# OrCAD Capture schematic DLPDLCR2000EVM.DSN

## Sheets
1 P05: SDRAM memory: size D
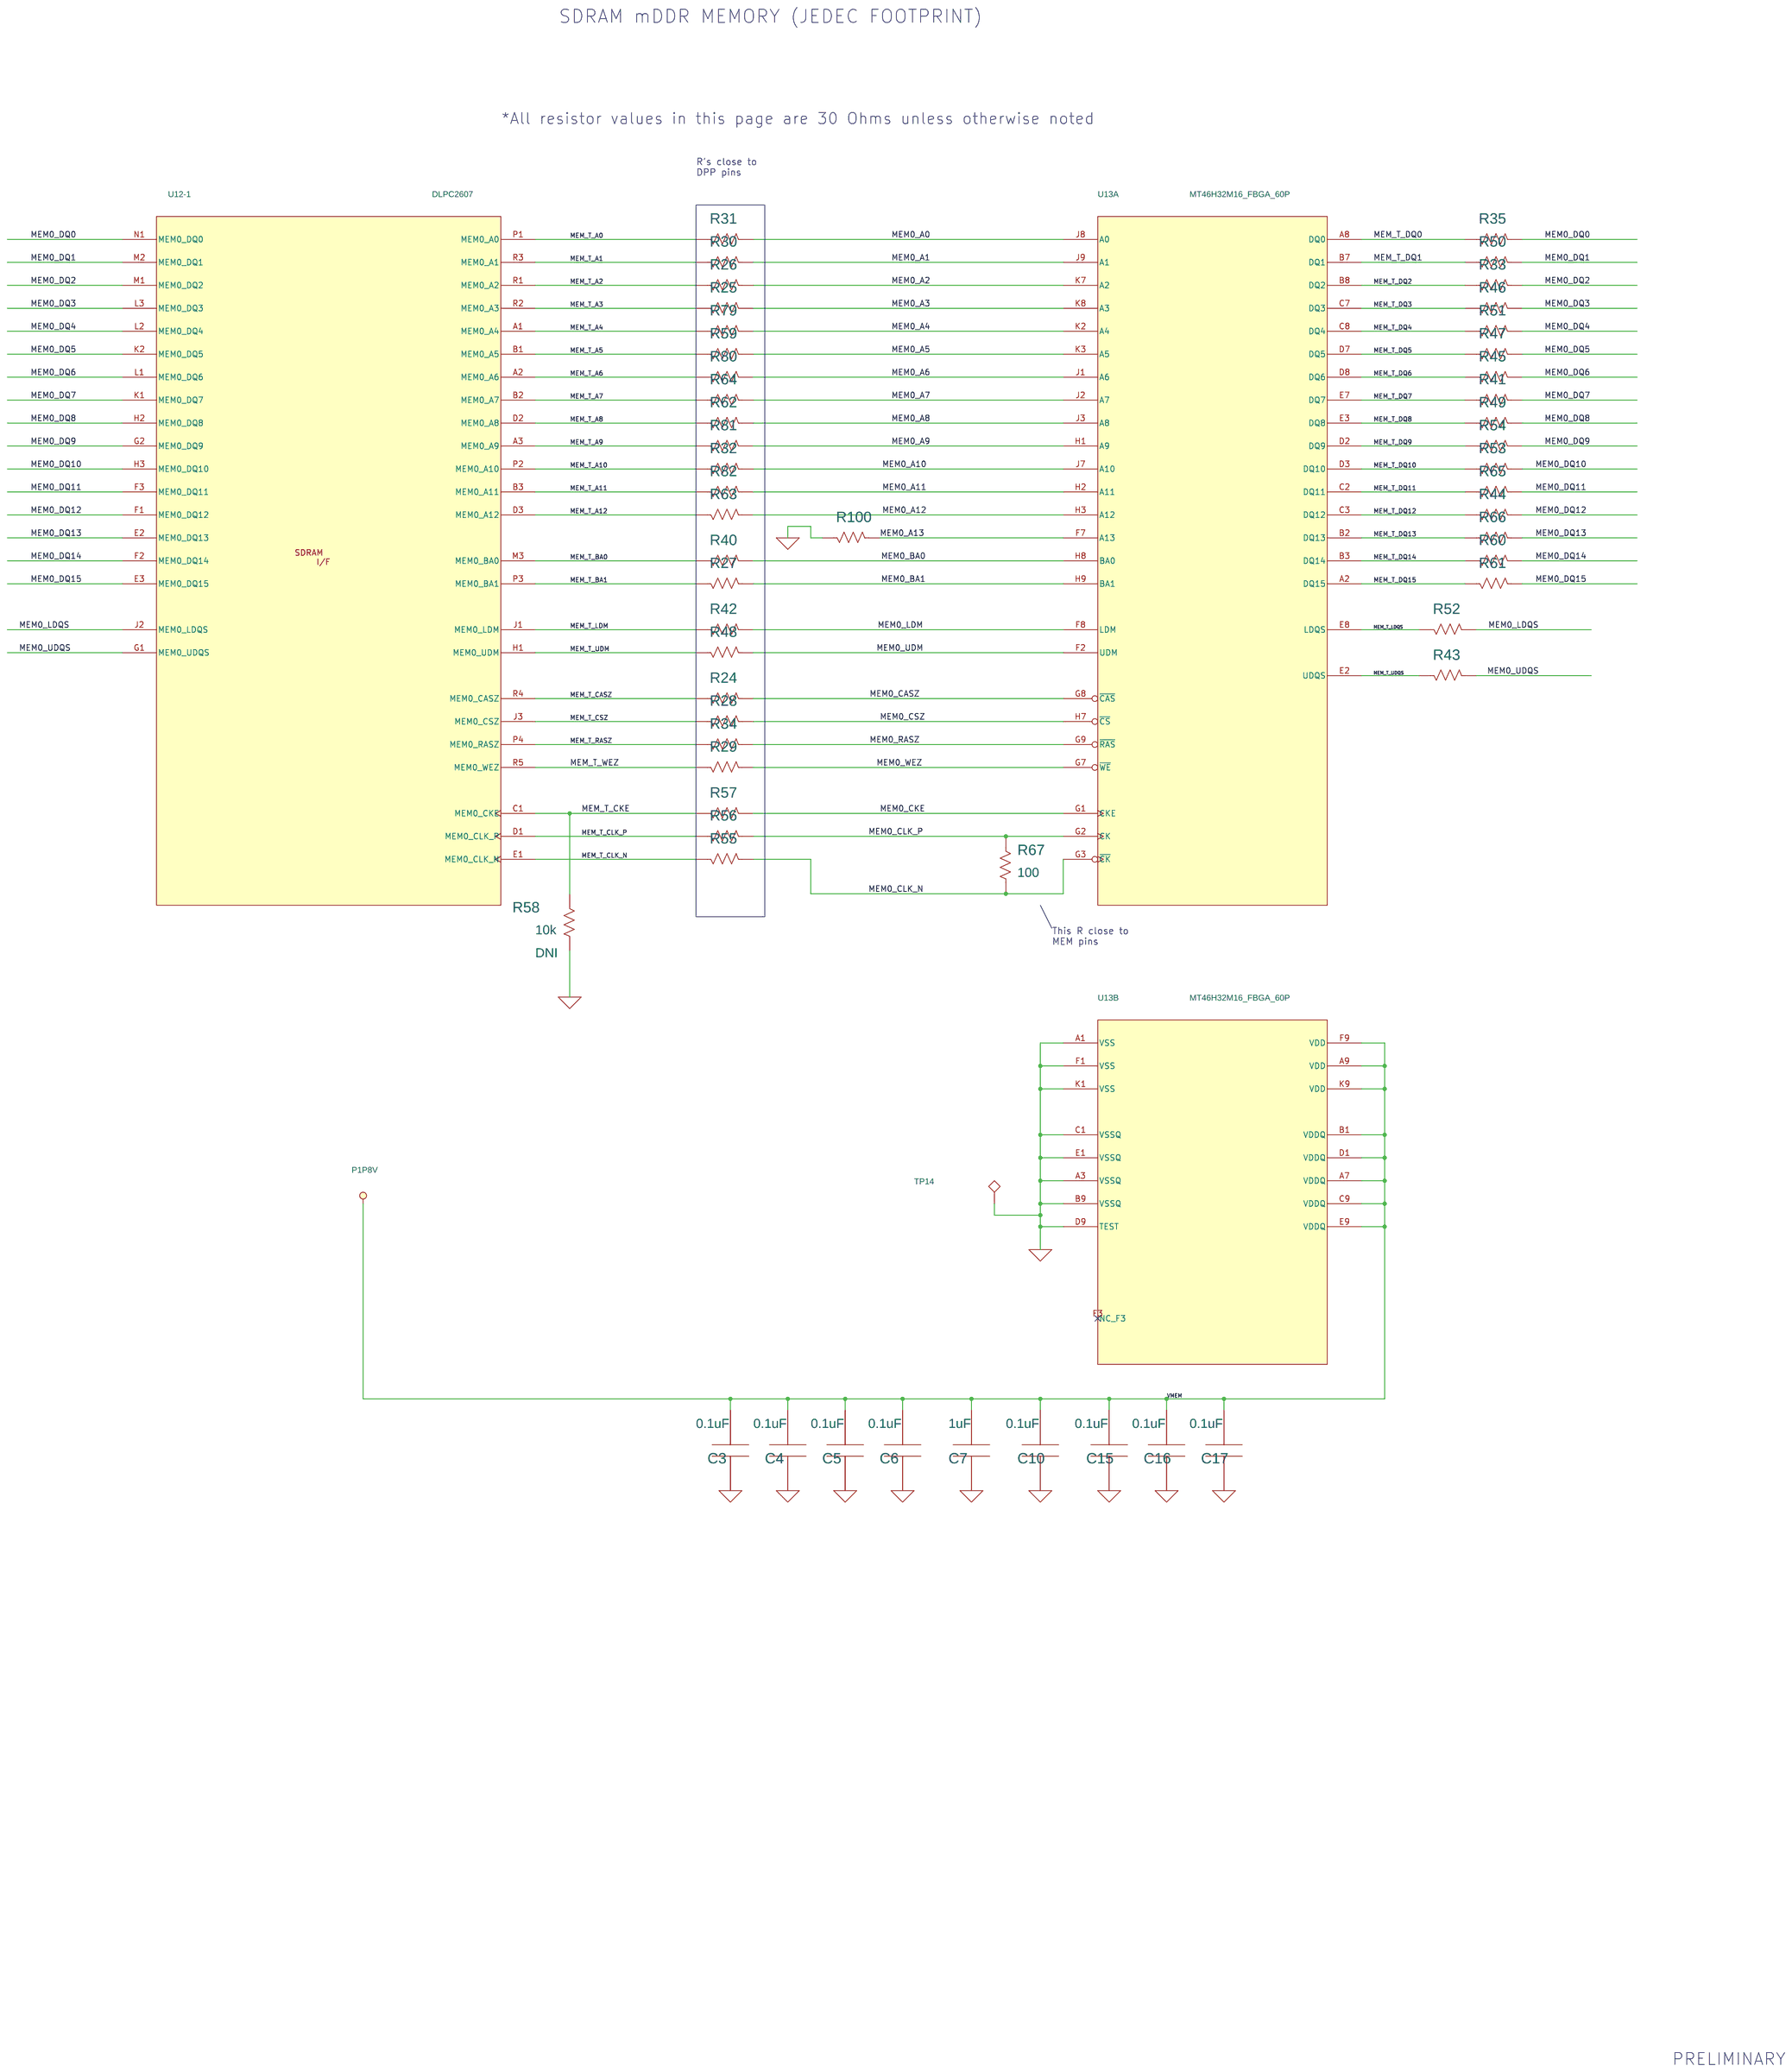
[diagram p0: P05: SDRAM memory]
2 P07: Revisions
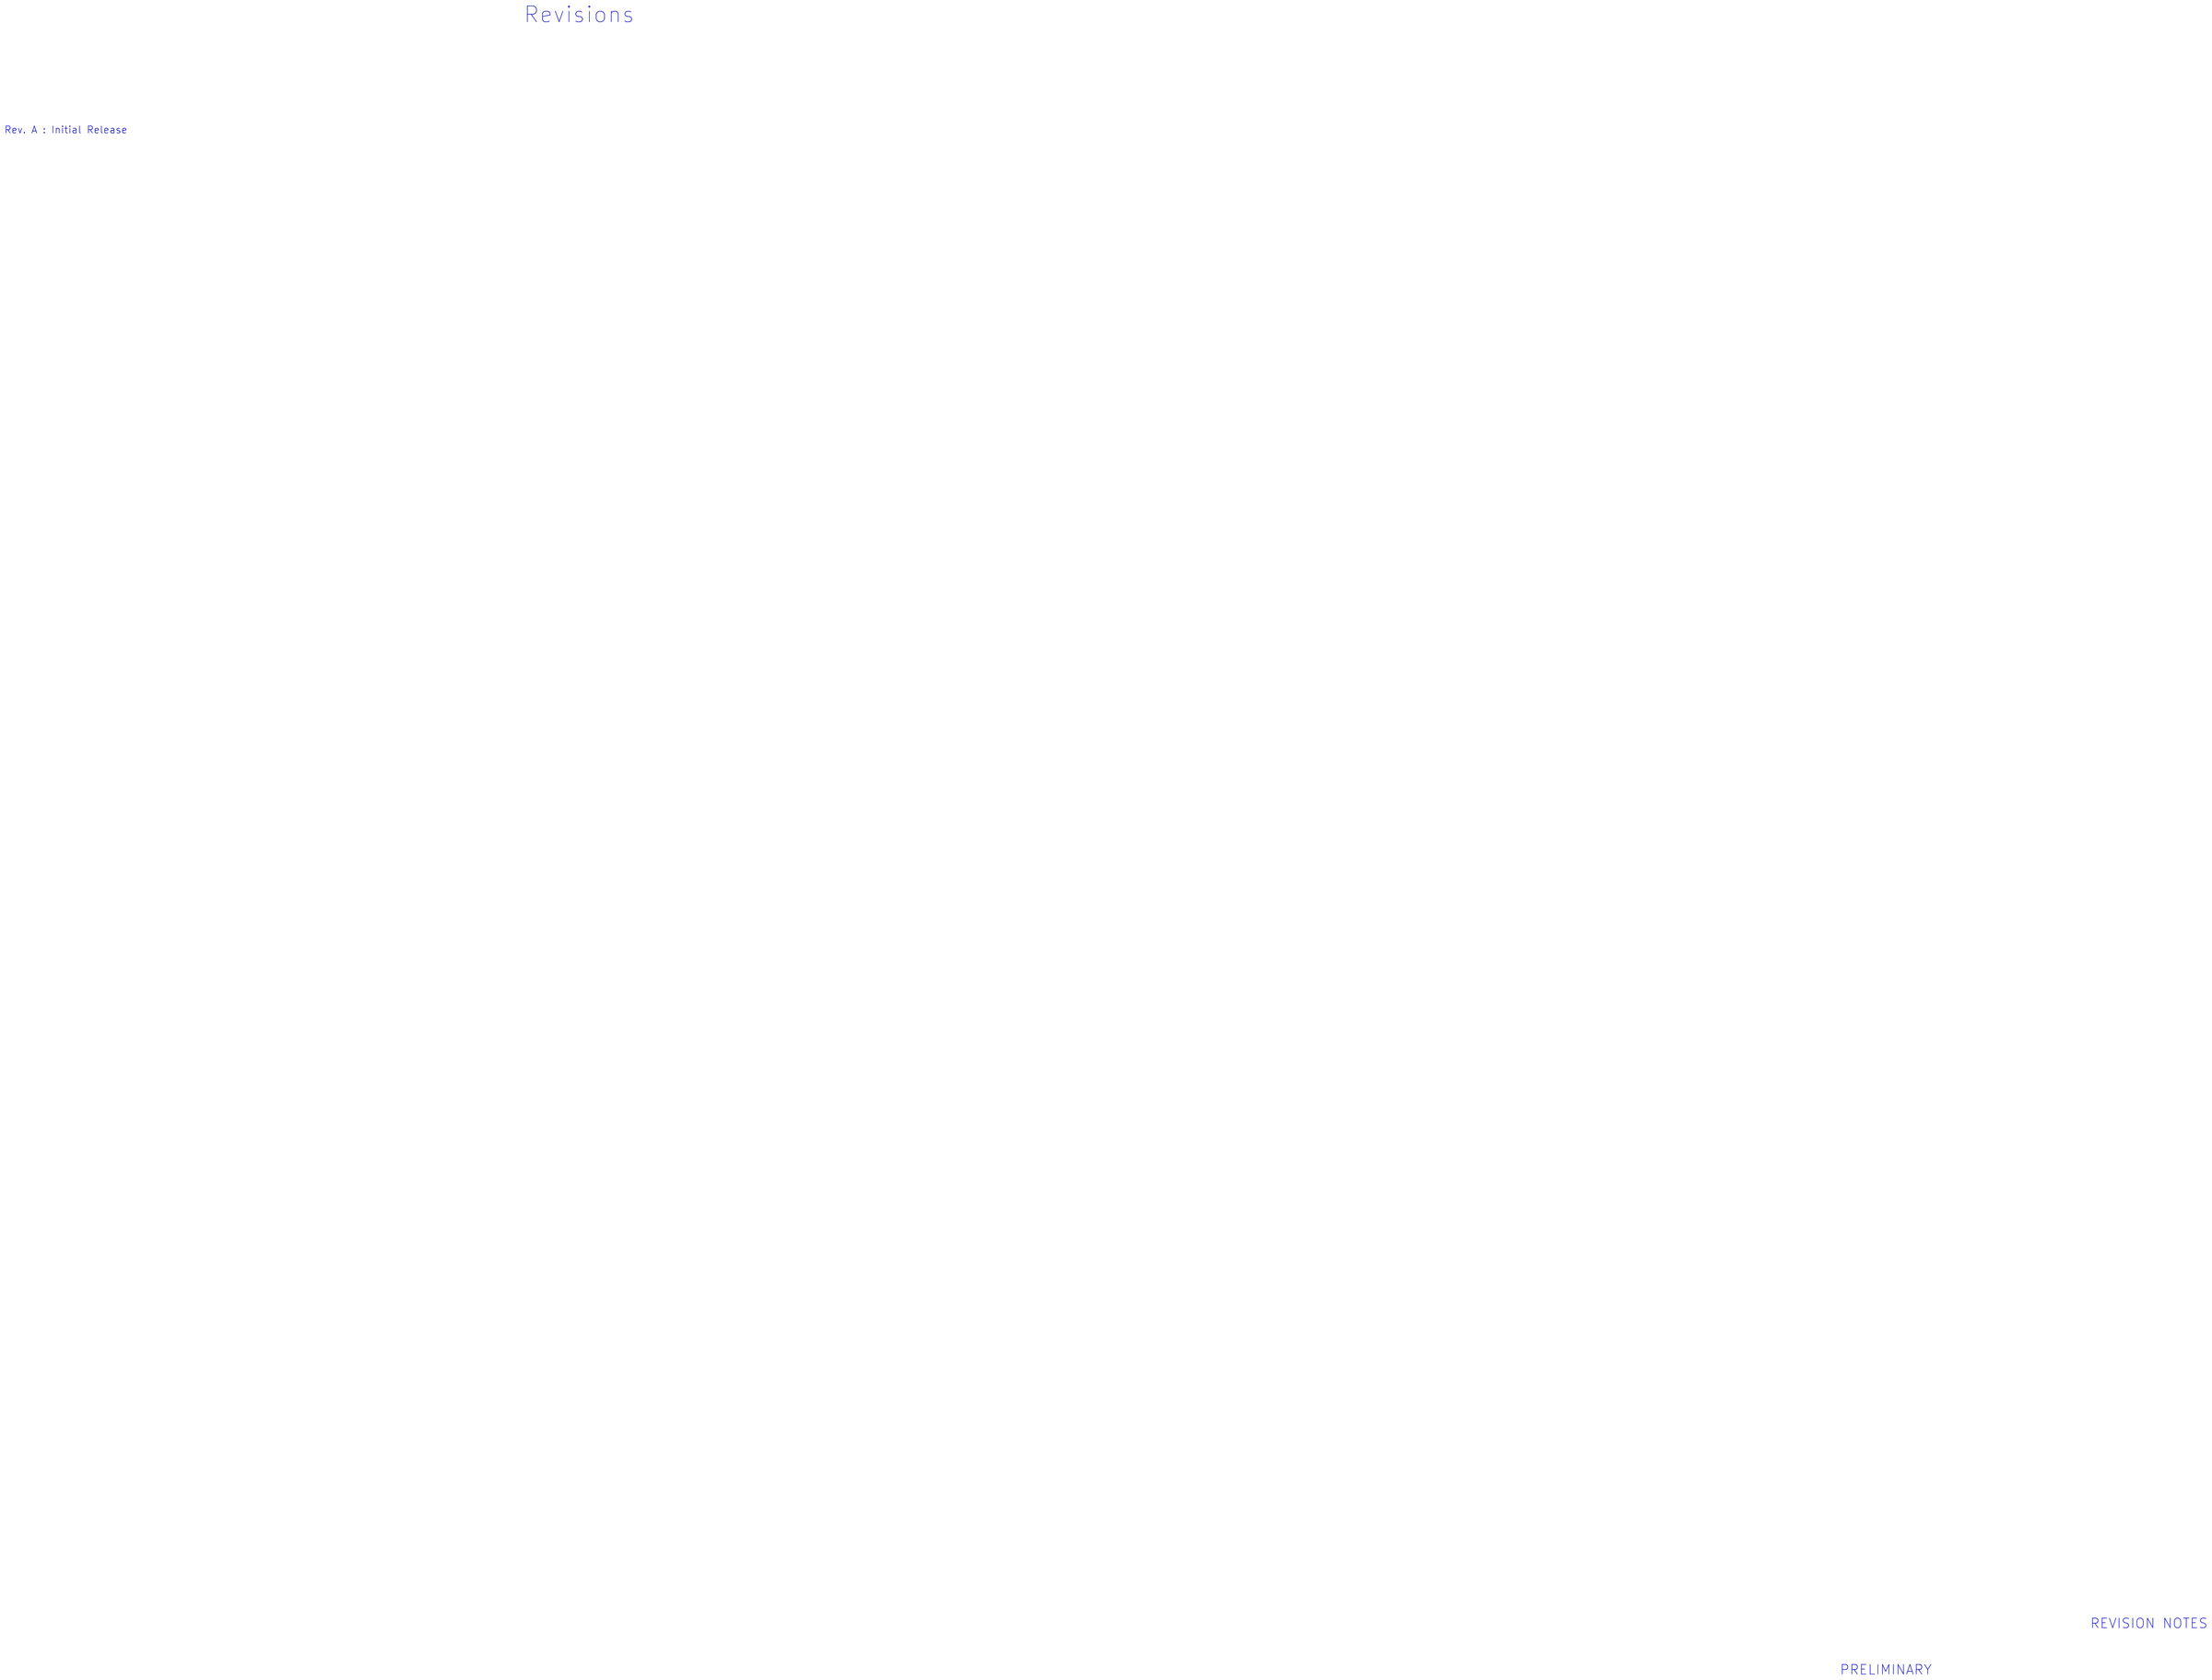
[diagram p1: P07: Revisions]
3 P04: DLPC2607/FLASH: size D
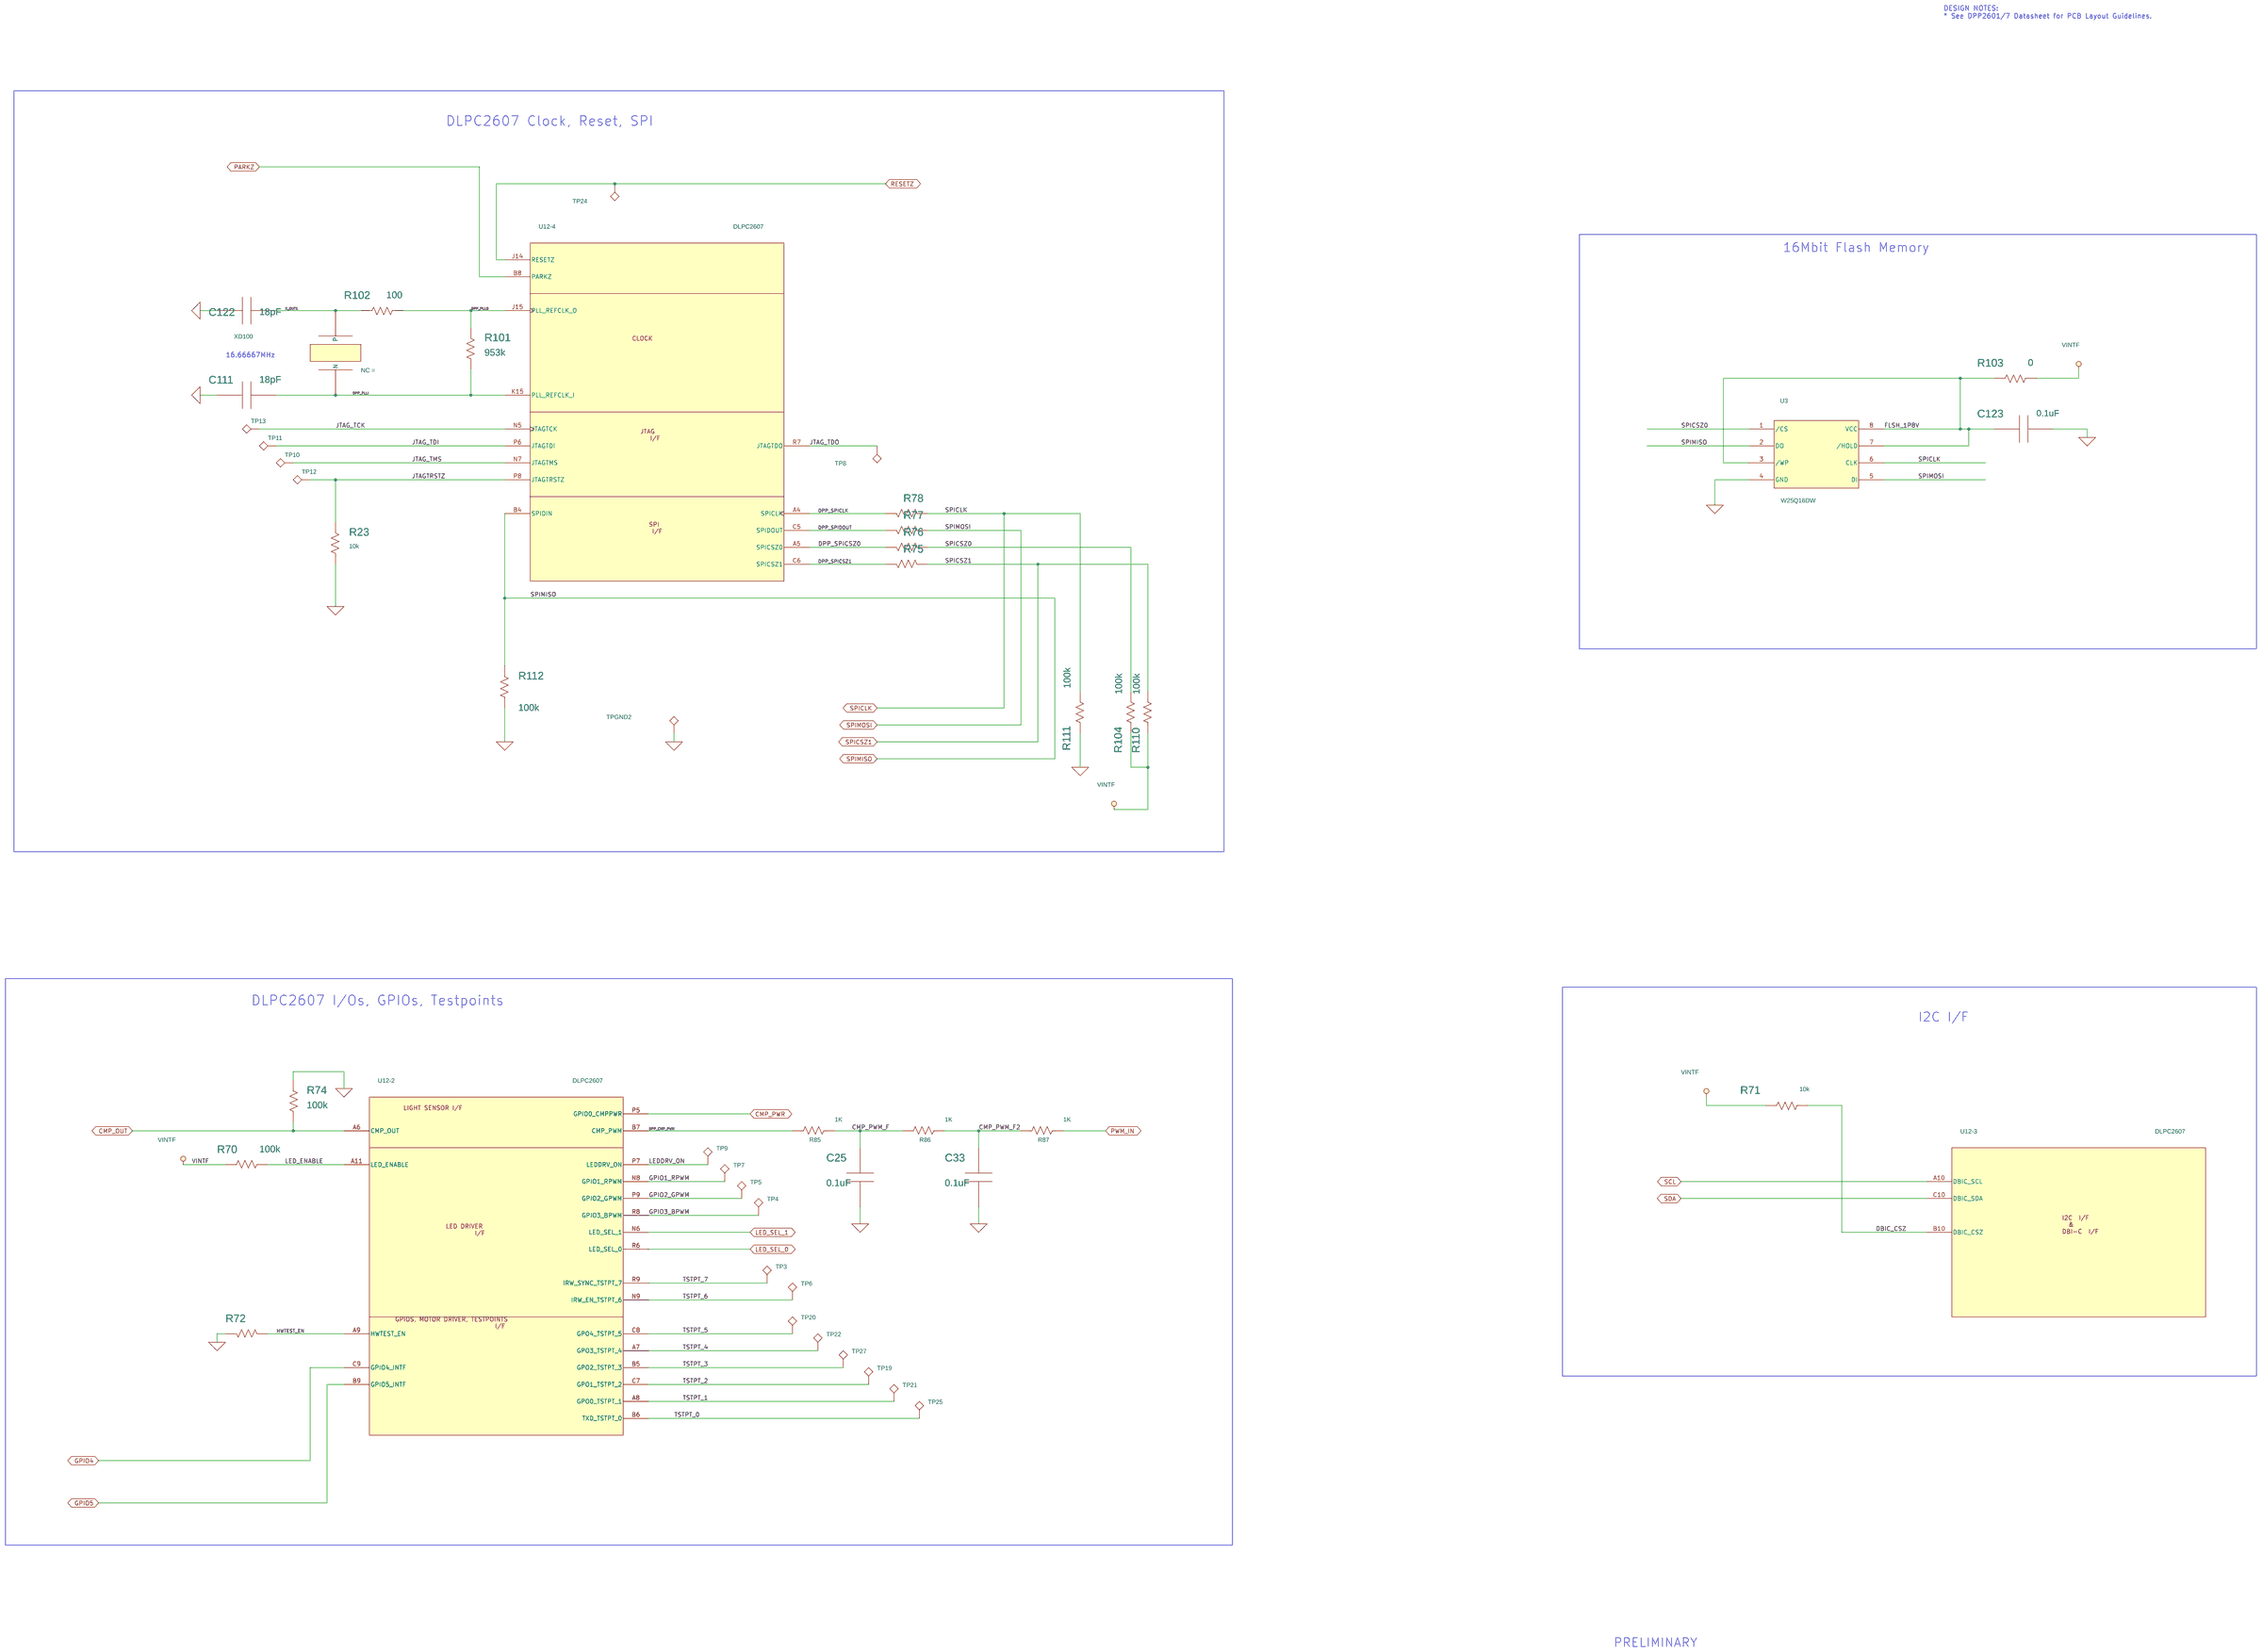
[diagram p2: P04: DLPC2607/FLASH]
4 P06: DLPC2607/DMD: size D
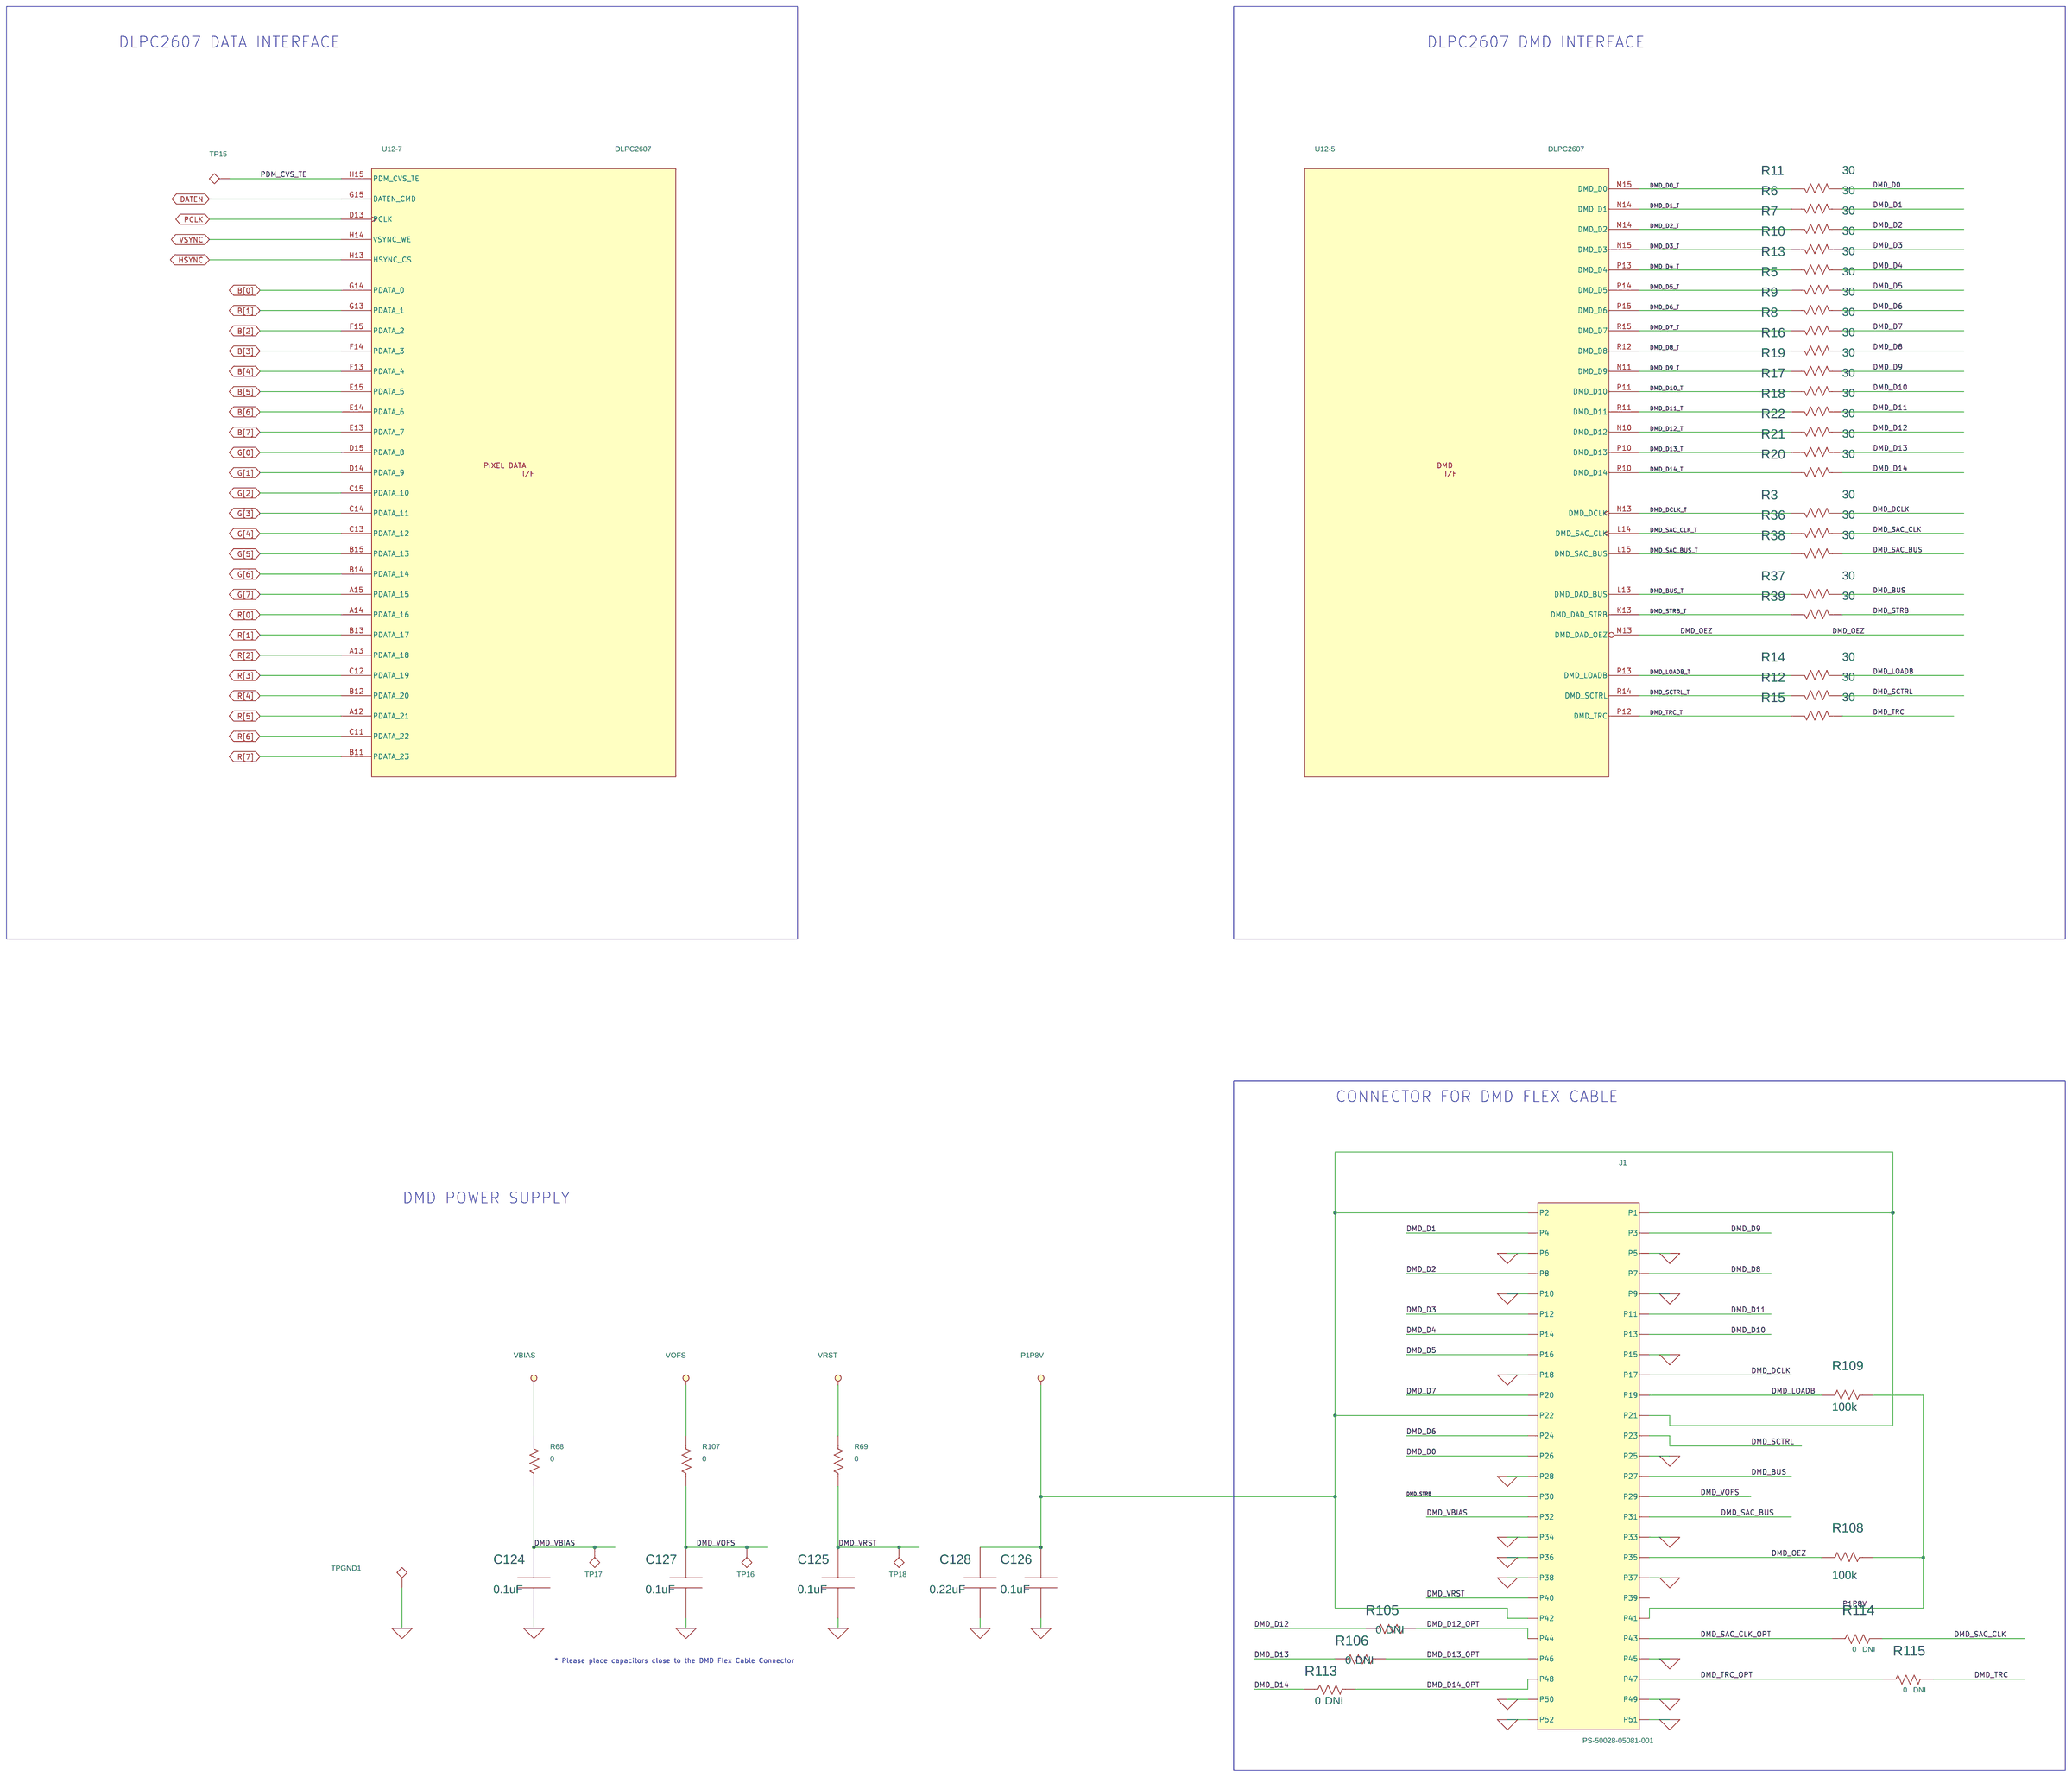
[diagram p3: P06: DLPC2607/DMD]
5 P02: Power-PAD1000/DLPC2607: size D
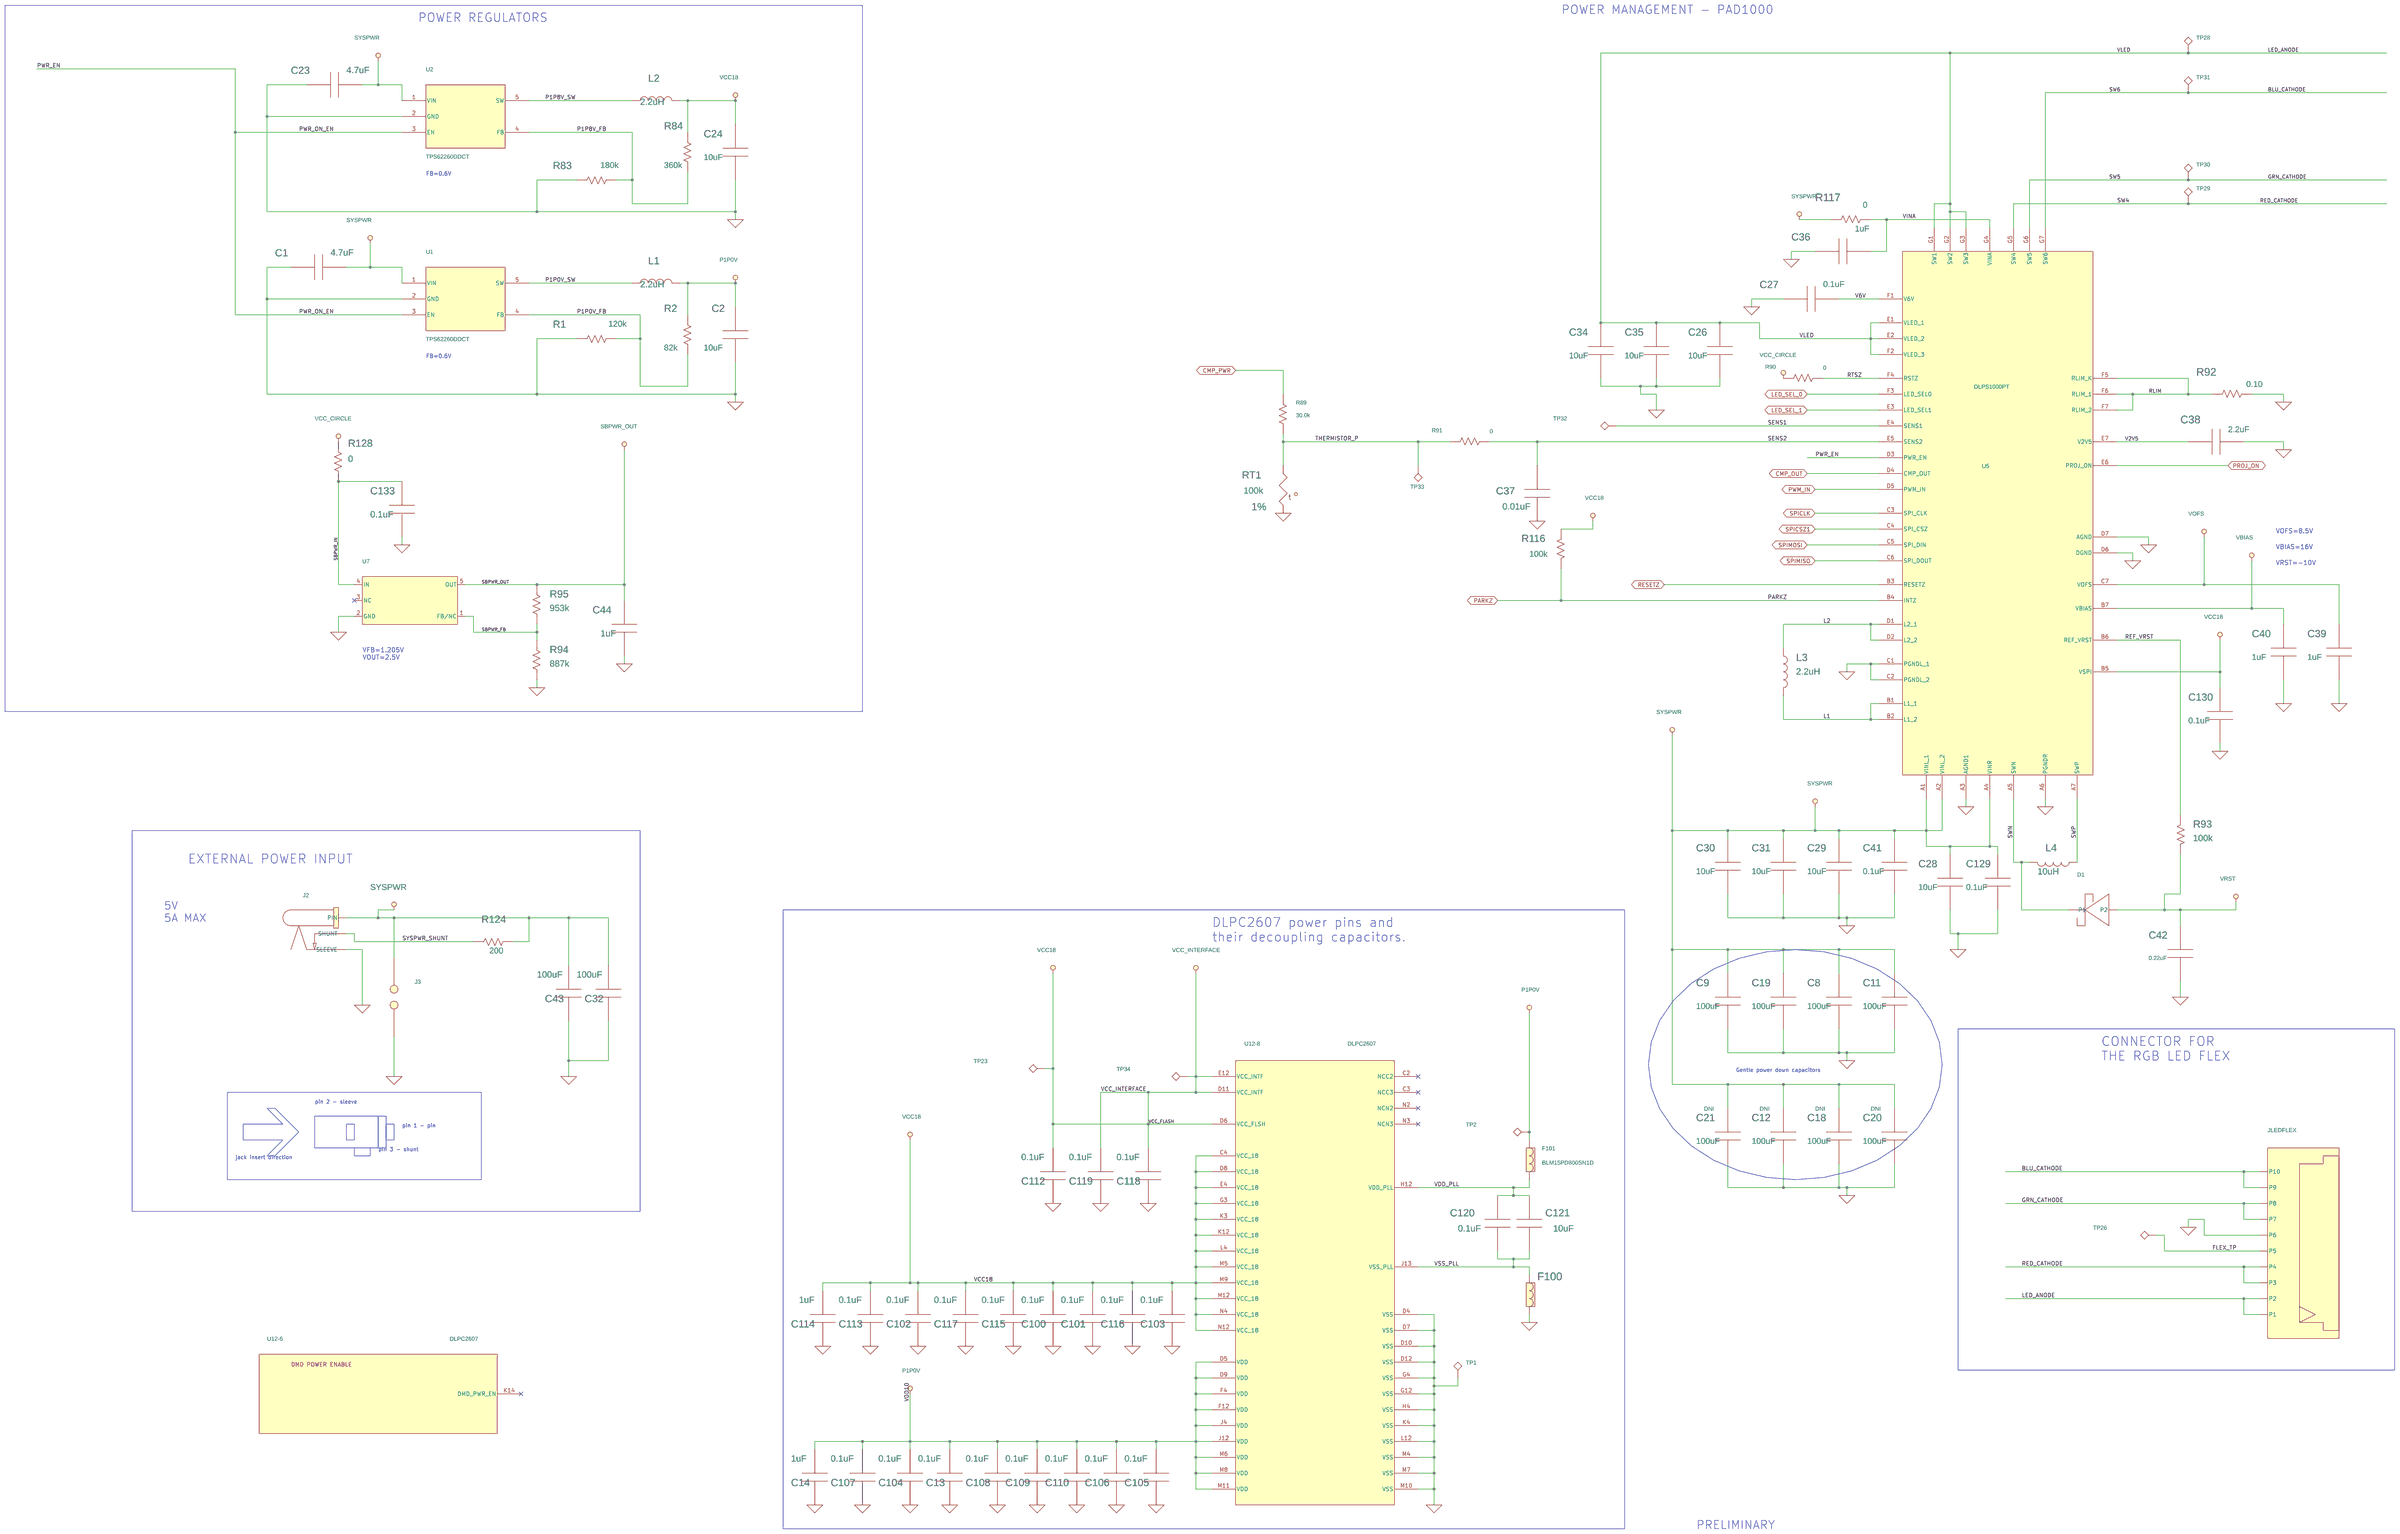
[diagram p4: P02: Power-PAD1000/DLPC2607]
6 P03: Interface Connection: size D
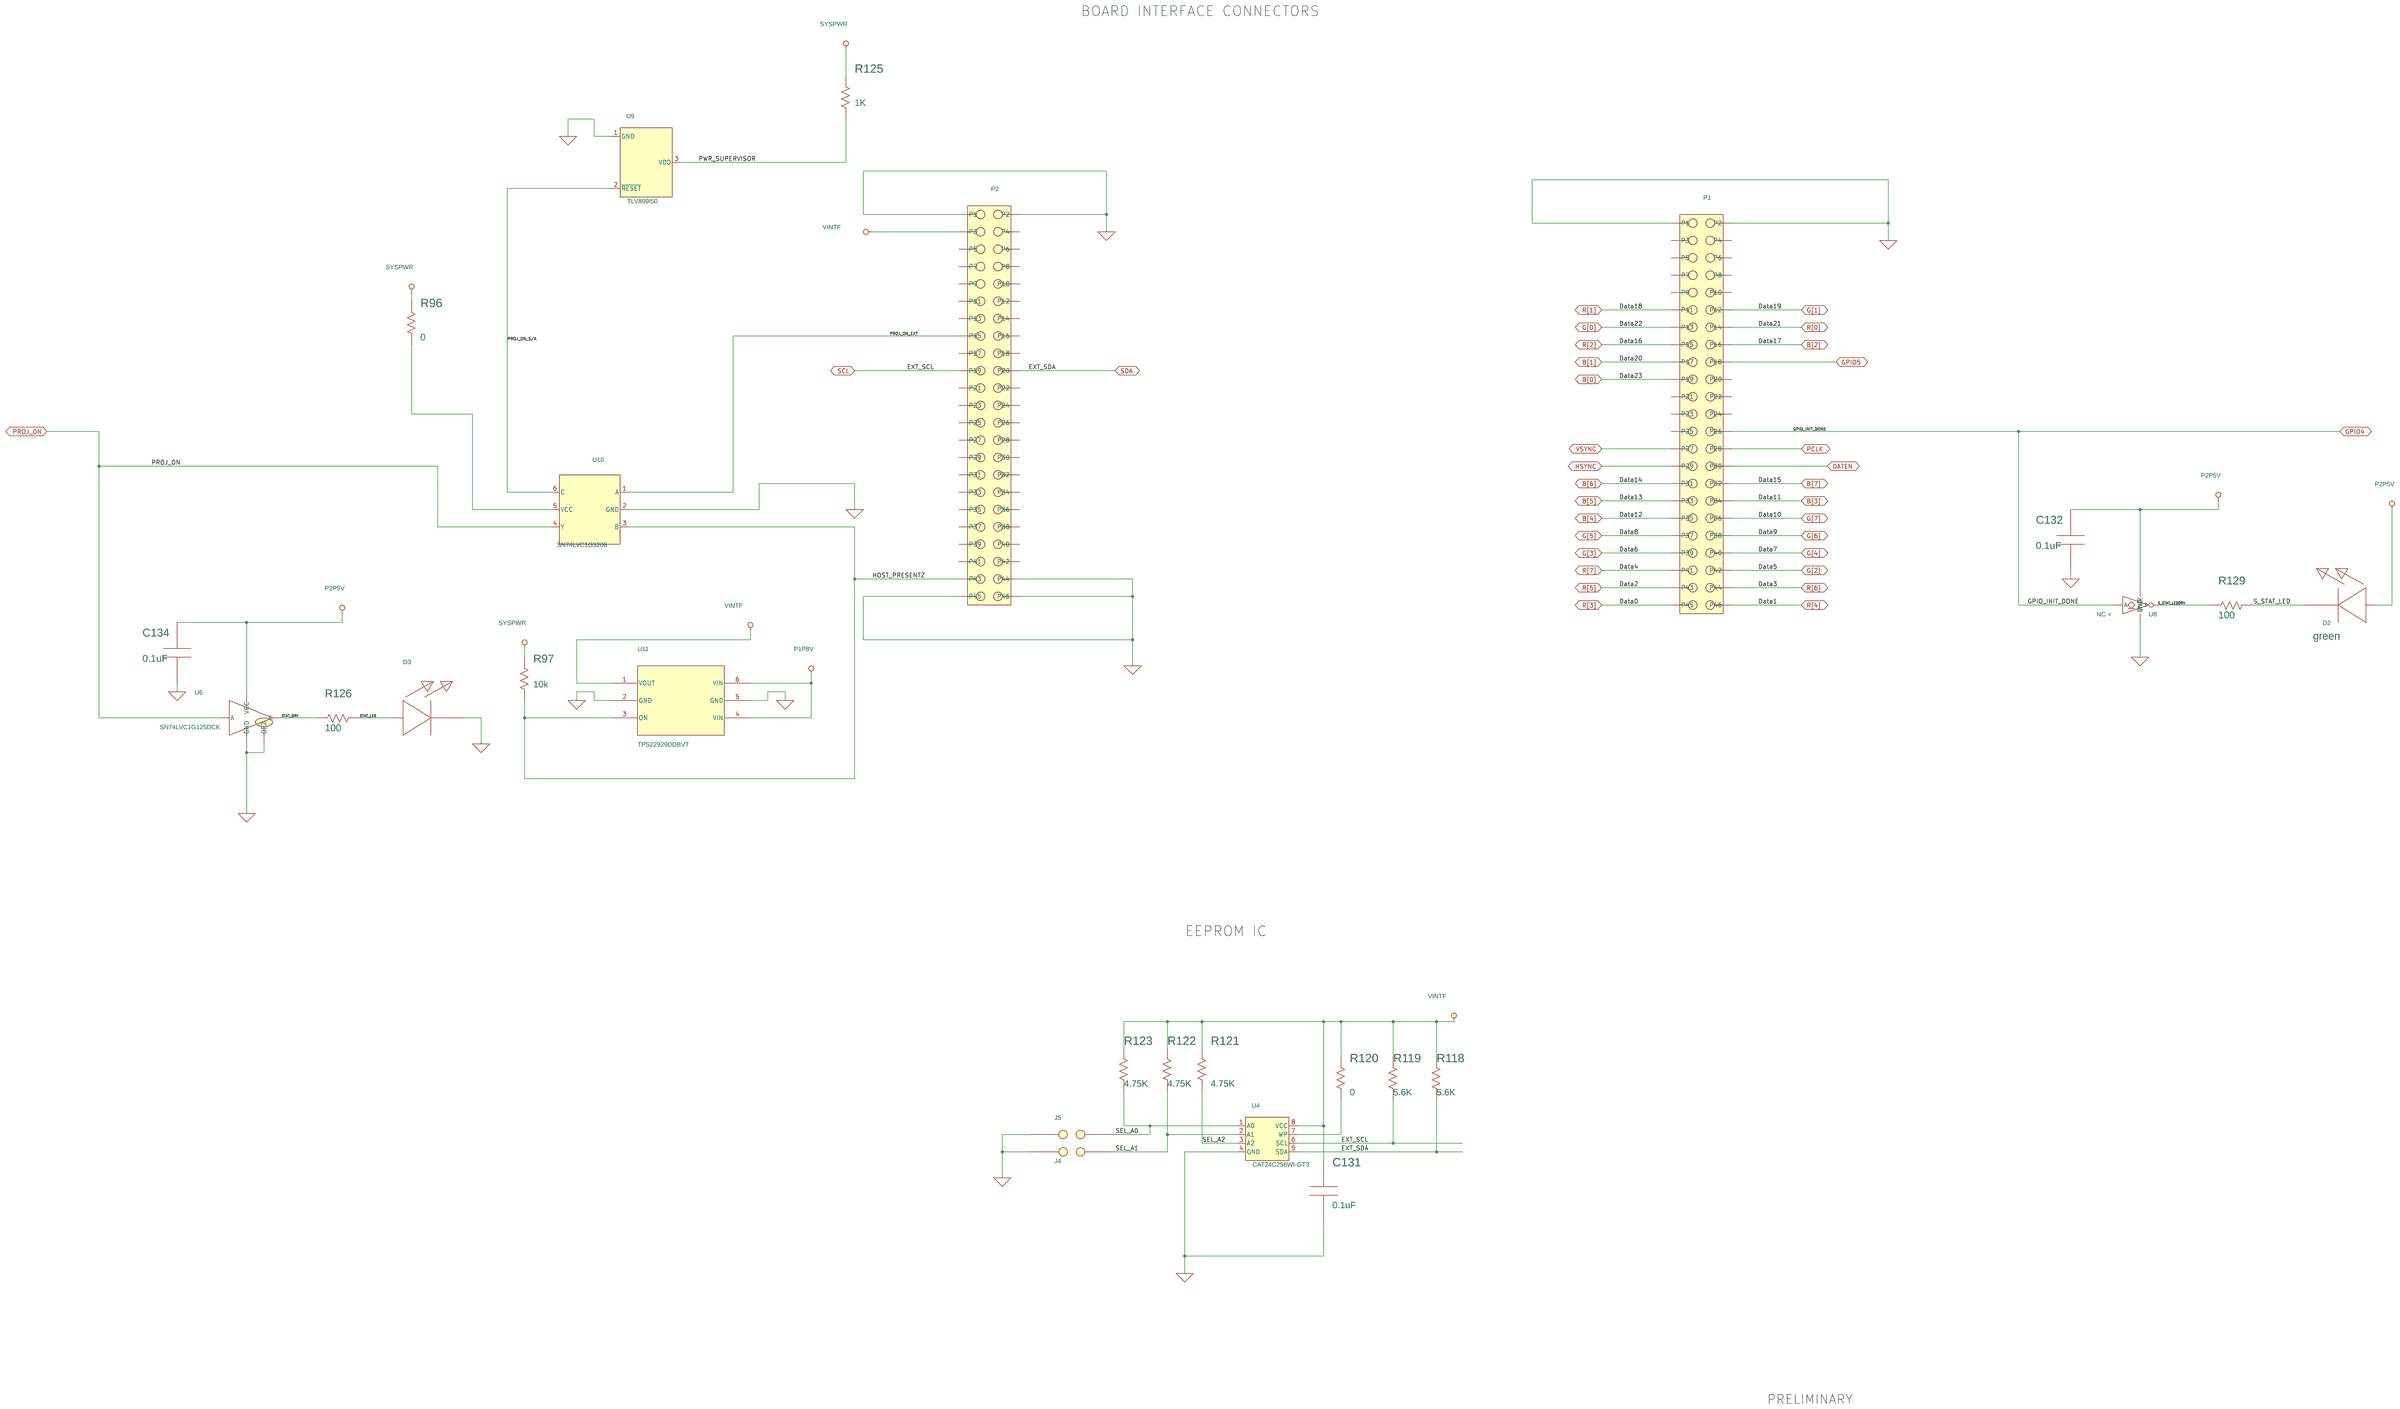
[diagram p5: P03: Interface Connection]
7 P01: DLPDLCR2000 EVM Title Page: rev: A
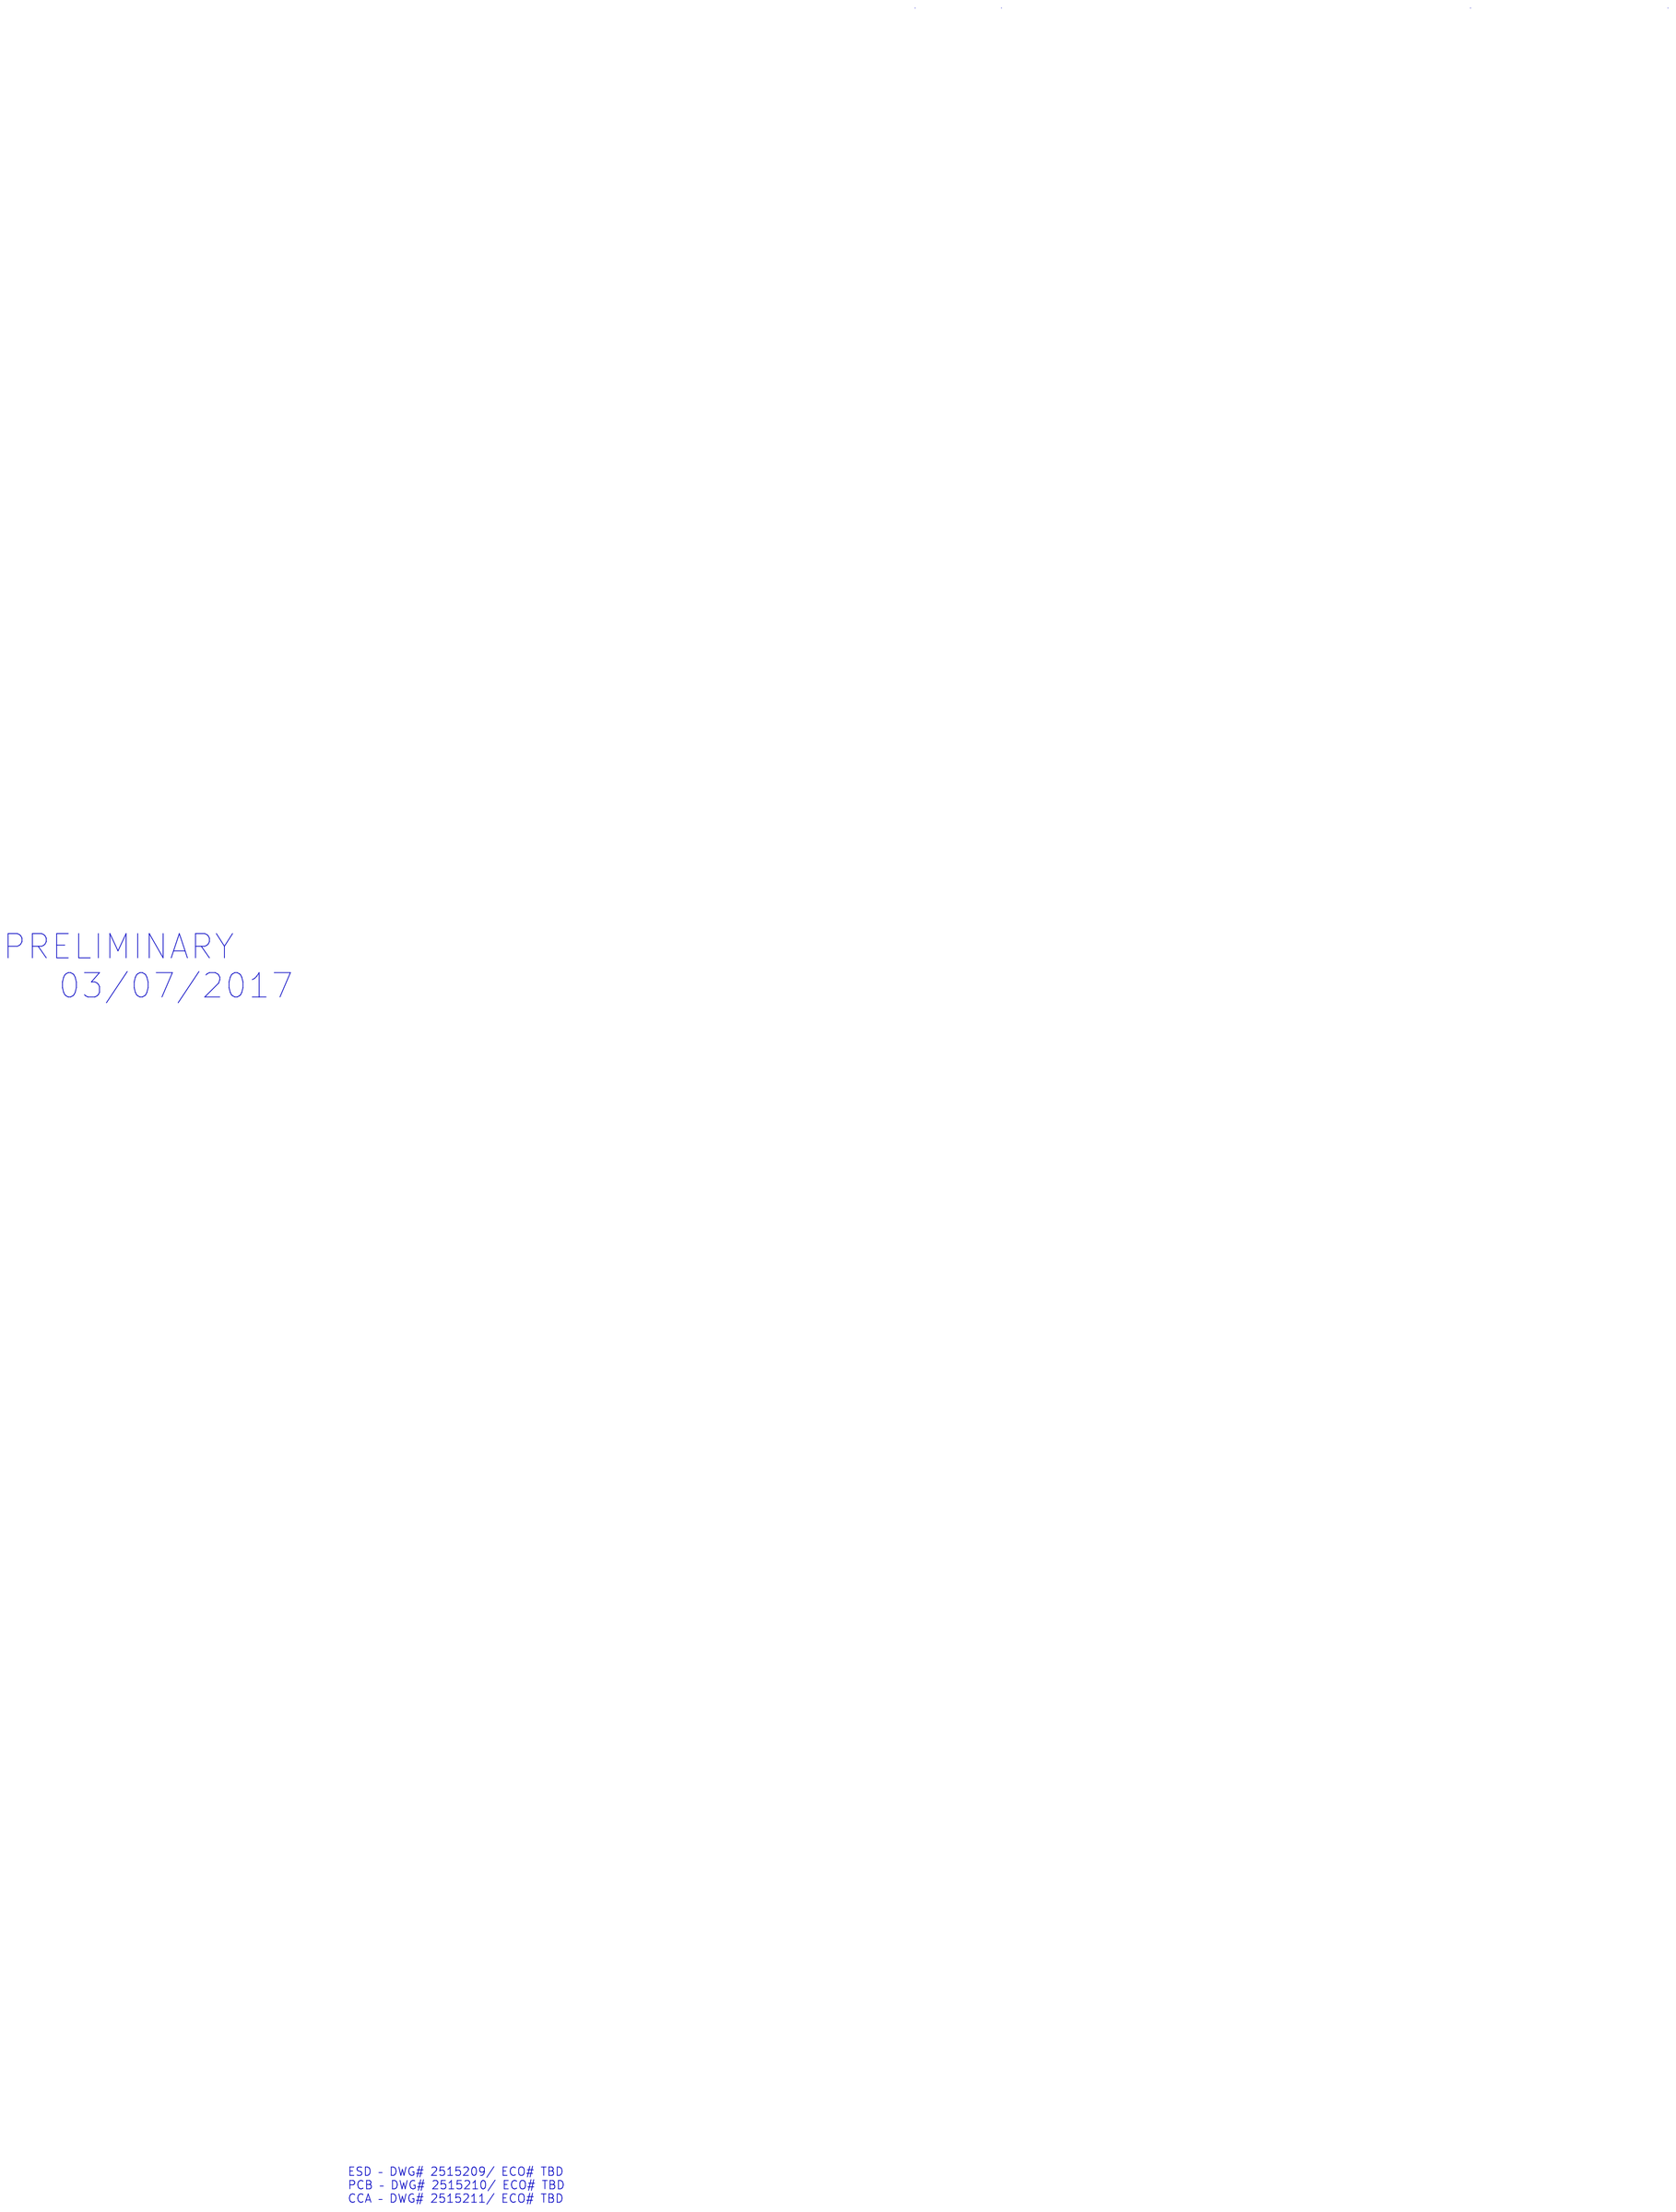
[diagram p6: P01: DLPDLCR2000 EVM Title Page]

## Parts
sheet P02: Power-PAD1000/DLPC2607
C1  4.7uF  [0402]
C2  10uF  [0603]
C8  100uF  [1210]
C9  100uF  [1210]
C11  100uF  [1210]
C12  100uF  [1210]
C13  0.1uF  [0201]
C14  1uF  [0201]
C18  100uF  [1210]
C19  100uF  [1210]
C20  100uF  [1210]
C21  100uF  [1210]
C23  4.7uF  [0402]
C24  10uF  [0603]
C26  10uF  [0603]
C27  0.1uF  [0402_AVXA]
C28  10uF  [0603]
C29  10uF  [0603]
C30  10uF  [0603]
C31  10uF  [0603]
C32  100uF  [1210]
C34  10uF  [0603]
C35  10uF  [0603]
C36  1uF  [0402]
C37  0.01uF  [0402]
C38  2.2uF  [0402]
C39  1uF  [0402]
C40  1uF  [0603]
C41  0.1uF  [0402_AVXA]
C42  0.22uF  [0402]
C43  100uF  [1210]
C44  1uF  [0402]
C100  0.1uF  [0201]
C101  0.1uF  [0201]
C102  0.1uF  [0201]
C103  0.1uF  [0201]
C104  0.1uF  [0201]
C105  0.1uF  [0201]
C106  0.1uF  [0201]
C107  0.1uF  [0201]
C108  0.1uF  [0201]
C109  0.1uF  [0201]
C110  0.1uF  [0201]
C112  0.1uF  [0201]
C113  0.1uF  [0201]
C114  1uF  [0201]
C115  0.1uF  [0201]
C116  0.1uF  [0201]
C117  0.1uF  [0201]
C118  0.1uF  [0201]
C119  0.1uF  [0201]
C120  0.1uF  [0201]
C121  10uF  [0603]
C129  0.1uF  [0402_AVXA]
C130  0.1uF  [0402_AVXA]
C133  0.1uF  [0402_AVXA]
D1  PMEG4002EL  [SOD882]
F100  BLM15PD800SN1D  [0402]
F101  BLM15PD800SN1D  [0402]
J2  Pwr Jack, 2.1mm pin  [PJ-002A]
J3  HDR,2P,1R  [HDR2P_1R]
JLEDFLEX  EM,CONN,10P,ZIF  [CON_SMRT_52893-1095_NO-GND]
L1  2.2uH  [1008_2p5mmx2mm]
L2  2.2uH  [1008_2p5mmx2mm]
L3  2.2uH  [Coilcraft_LPS3015]
L4  10uH  [0805]
R1  120k  [0402]
R2  82k  [0402]
R83  180k  [0402]
R84  360k  [0402]
R89  30.0k  [0402]
R90  0  [0402]
R91  0  [0402]
R92  0.10  [0603]
R93  100k  [0402]
R94  887k  [0402]
R95  953k  [0402]
R116  100k  [0402]
R117  0  [0402]
R124  200  [0805]
R128  0  [0402]
RT1  100k  [0402]
TP1  TP,20mil PAD  [20mil_PAD]
TP2  TP,12mil Drill,32mil Pad  [HOLE_PLATED_12mil_DRILL_32mil_PAD]
TP23  TP,12mil Drill,32mil Pad  [HOLE_PLATED_12mil_DRILL_32mil_PAD]
TP26  TP,20mil PAD  [20mil_PAD]
TP28  TP,12mil Drill,32mil Pad  [HOLE_PLATED_12mil_DRILL_32mil_PAD]
TP29  TP,12mil Drill,32mil Pad  [HOLE_PLATED_12mil_DRILL_32mil_PAD]
TP30  TP,12mil Drill,32mil Pad  [HOLE_PLATED_12mil_DRILL_32mil_PAD]
TP31  TP,12mil Drill,32mil Pad  [HOLE_PLATED_12mil_DRILL_32mil_PAD]
TP32  TP,20mil PAD  [20mil_PAD]
TP33  TP,20mil PAD  [20mil_PAD]
TP34  TP,12mil Drill,32mil Pad  [HOLE_PLATED_12mil_DRILL_32mil_PAD]
U1  TPS62260DDCT  [TSOT-23_DDC_R-PDSO-G5]
U2  TPS62260DDCT  [TSOT-23_DDC_R-PDSO-G5]
U5  TIDLP,PAD1000  [PAD1000]
U7  TPS71501DCK  [U_5_DCK]
sheet P03: Interface Connection
C131  0.1uF  [0402_AVXA]
C132  0.1uF  [0402_AVXA]
C134  0.1uF  [0402_AVXA]
D2  green  [1206]
D3  green  [1206]
J4  HDR,2P,1R  [HDR2P_1R]
J5  HDR,2P,1R  [HDR2P_1R]
P1  EM,HDR,46P,2R,2x  [PRT_12790]
P2  EM,HDR,46P,2R,2x  [PRT_12790]
R96  0  [0402]
R97  10k  [0402]
R118  5.6K  [0402]
R119  5.6K  [0402]
R120  0  [0402]
R121  4.75K  [0402]
R122  4.75K  [0402]
R123  4.75K  [0402]
R125  1K  [0402]
R126  100  [0402]
R129  100  [0402]
U4  CAT24C256WI-GT3  [8-SOIC]
U6  SN74LVC1G125DCK  [U_5_DCK]
U8  LOG,INV,OPENDRN,SN74AUP1G06DCK  [U_5_DCK]
U9  TLV809I50  [TLV809I50]
U10  SN74LVC1G3208  [DCK_SC70_6]
U11  TPS22929DDBVT  [SOT23-6_DBV_R-PDSO-G6]
sheet P04: DLPC2607/FLASH
C25  0.1uF  [0402_AVXA]
C33  0.1uF  [0402_AVXA]
C111  18pF  [0402]
C122  18pF  [0402]
C123  0.1uF  [0402_AVXA]
R23  10k  [0402]
R70  100k  [0402]
R71  10k  [0402]
R72  30.1  [0402]
R74  100k  [0402]
R75  30.1  [0402]
R76  30.1  [0402]
R77  30.1  [0402]
R78  30.1  [0402]
R85  1K  [0402]
R86  1K  [0402]
R87  1K  [0402]
R101  953k  [0402]
R102  100  [0402]
R103  0  [0402]
R104  100k  [0402]
R110  100k  [0402]
R111  100k  [0402]
R112  100k  [0402]
TP3  TP,20mil PAD  [20mil_PAD]
TP4  TP,20mil PAD  [20mil_PAD]
TP5  TP,20mil PAD  [20mil_PAD]
TP6  TP,20mil PAD  [20mil_PAD]
TP7  TP,20mil PAD  [20mil_PAD]
TP8  TP,20mil PAD  [20mil_PAD]
TP9  TP,20mil PAD  [20mil_PAD]
TP10  TP,20mil PAD  [20mil_PAD]
TP11  TP,20mil PAD  [20mil_PAD]
TP12  TP,20mil PAD  [20mil_PAD]
TP13  TP,20mil PAD  [20mil_PAD]
TP19  TP,20mil PAD  [20mil_PAD]
TP20  TP,20mil PAD  [20mil_PAD]
TP21  TP,20mil PAD  [20mil_PAD]
TP22  TP,20mil PAD  [20mil_PAD]
TP24  TP,20mil PAD  [20mil_PAD]
TP25  TP,20mil PAD  [20mil_PAD]
TP27  TP,20mil PAD  [20mil_PAD]
TPGND2  TP40  [TP40]
U3  W25Q16DW  [W25Q16DW_WINBOND]
U12  DLPC2607  [DPP2607]  (sections -1,-2,-3,-4,-5,-6,-7,-8)
XD100  16.66667MHz  [4_SMD]
sheet P05: SDRAM memory
C3  0.1uF  [0201]
C4  0.1uF  [0201]
C5  0.1uF  [0201]
C6  0.1uF  [0201]
C7  1uF  [0201]
C10  0.1uF  [0201]
C15  0.1uF  [0201]
C16  0.1uF  [0201]
C17  0.1uF  [0201]
R24  30  [0201_R]
R25  30  [0201_R]
R26  30  [0201_R]
R27  30  [0201_R]
R28  30  [0201_R]
R29  30  [0201_R]
R30  30  [0201_R]
R31  30  [0201_R]
R32  30  [0201_R]
R33  30  [0201_R]
R34  30  [0201_R]
R35  30  [0201_R]
R40  30  [0201_R]
R41  30  [0201_R]
R42  30  [0201_R]
R43  30  [0201_R]
R44  30  [0201_R]
R45  30  [0201_R]
R46  30  [0201_R]
R47  30  [0201_R]
R48  30  [0201_R]
R49  30  [0201_R]
R50  30  [0201_R]
R51  30  [0201_R]
R52  30  [0201_R]
R53  30  [0201_R]
R54  30  [0201_R]
R55  30  [0201_R]
R56  30  [0201_R]
R57  30  [0201_R]
R58  10k  [0201]
R59  30  [0201_R]
R60  30  [0201_R]
R61  30  [0201_R]
R62  30  [0201_R]
R63  30  [0201_R]
R64  30  [0201_R]
R65  30  [0201_R]
R66  30  [0201_R]
R67  100  [0201]
R79  30  [0201_R]
R80  30  [0201_R]
R81  30  [0201_R]
R82  30  [0201_R]
R100  30  [0201_R]
TP14  TP,20mil PAD  [20mil_PAD]
U13  MT46H32M16_FBGA_60P  [VFBGA_60]  (sections A,B)
sheet P06: DLPC2607/DMD
C124  0.1uF  [0402]
C125  0.1uF  [0402]
C126  0.1uF  [0402_AVXA]
C127  0.1uF  [0402]
C128  0.22uF  [0603]
J1  PS-50028-05081-001  [CON_SMVT_50028-50]
R3  30  [0201_R]
R5  30  [0201_R]
R6  30  [0201_R]
R7  30  [0201_R]
R8  30  [0201_R]
R9  30  [0201_R]
R10  30  [0201_R]
R11  30  [0201_R]
R12  30  [0201_R]
R13  30  [0201_R]
R14  30  [0201_R]
R15  30  [0201_R]
R16  30  [0201_R]
R17  30  [0201_R]
R18  30  [0201_R]
R19  30  [0201_R]
R20  30  [0201_R]
R21  30  [0201_R]
R22  30  [0201_R]
R36  30  [0201_R]
R37  30  [0201_R]
R38  30  [0201_R]
R39  30  [0201_R]
R68  0  [0402]
R69  0  [0402]
R105  0  [0402]
R106  0  [0402]
R107  0  [0402]
R108  100k  [0402]
R109  100k  [0402]
R113  0  [0402]
R114  0  [0402]
R115  0  [0402]
TP15  TP,20mil PAD  [20mil_PAD]
TP16  TP,12mil Drill,32mil Pad  [HOLE_PLATED_12mil_DRILL_32mil_PAD]
TP17  TP,12mil Drill,32mil Pad  [HOLE_PLATED_12mil_DRILL_32mil_PAD]
TP18  TP,12mil Drill,32mil Pad  [HOLE_PLATED_12mil_DRILL_32mil_PAD]
TPGND1  TP40  [TP40]

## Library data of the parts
C1 C23 = PAS,CAP,NP,large: DigiKey: 445-7395-1-ND; DigiReel: 445-7395-6-ND; Family: passive; Index PN: 1073; Lead Style: SMT; MFG: TDK; Material: x5r; P/D_NUM: C1005X5R0J475M; Part Number: C1005X5R0J475M; Part Specific: CAP CER 4.7UF 6.3V 20% X5R 0402; Type: capacitor; VENDOR: TDK; VPC: 6.3V
C2 C24 C34 = PAS,CAP,NP,large: DigiKey: 445-4112-1-ND; DigiReel: 445-4112-6-ND; Family: passive; Index PN: 906; Lead Style: SMT; MFG: TDK; Material: x5r; P/D_NUM: C1608X5R0J106M080AB; Part Number: C1608X5R0J106M080AB; Part Specific: CAP CERAMIC 10UF 6.3V X5R 0603; TOLERANCE: 20%; Type: capacitor; VENDOR: TDK; VPC: 6.3V; Voltage: 16V
C8 C9 C11 C19 = PAS,CAP,NP,large: DigiKey: 587-3152-1-ND; DigiReel: 587-3152-2-ND; Family: passive; Index PN: 1227; Lead Style: SMT; MFG: Taiyo Yuden; Material: x5r; P/D_NUM: EMK325ABJ107MM-T; Part Number: EMK325ABJ107MM-T; Part Specific: CAP CER 100UF 16V 20% X5R 1210; TOLERANCE: 20%; Type: capacitor; VENDOR: Taiyo Yuden; VPC: 16V; Voltage: 10V
C12 C18 C20 C21 = PAS,CAP,NP,large: DigiKey: 587-3152-1-ND; DigiReel: 587-3152-2-ND; Family: passive; Index PN: 1227; Install: DNI; Lead Style: SMT; MFG: Taiyo Yuden; Material: x5r; P/D_NUM: EMK325ABJ107MM-T; Part Number: EMK325ABJ107MM-T; Part Specific: CAP CER 100UF 16V 20% X5R 1210; TOLERANCE: 20%; Type: capacitor; VENDOR: Taiyo Yuden; VPC: 16V; Voltage: 10V
C13 C100-C110 C112 C113 C115-C120 = PAS,CAP,NP,large: DigiKey: 445-15903-1-ND; DigiReel: 445-15903-6-ND; Family: passive; Lead Style: SMT; MFG: TDK; Material: x7r; P/D_NUM: C0603X6S1C104K030BC; Part Number: C0603X6S1C104K030BC; Part Specific: CAP CER .1UF 16V X7R 0201; TOLERANCE: 10%; Type: capacitor; VENDOR: TDK; VPC: 16V
C14 C114 = PAS,CAP,NP,large: DigiKey: 445-8008-1-ND; DigiReel: 445-8008-2-ND; Family: passive; Lead Style: SMT; MFG: TDK; Material: x5r; P/D_NUM: C0603X5R0J105M030BC; Part Number: C0603X5R0J105M030BC; Part Specific: CAP CER 1.0UF 6.3V X5R 0201; TOLERANCE: 20%; Type: capacitor; VENDOR: TDK; VPC: 6.3V
C26 C28-C31 C35 = PAS,CAP,NP,large: DigiKey: 445-4112-1-ND; DigiReel: 445-4112-6-ND; Family: passive; Index PN: 906; Lead Style: SMT; MFG: TDK; Material: x5r; P/D_NUM: C1608X5R0J106M080AB; Part Number: C1608X5R0J106M080AB; Part Specific: CAP CERAMIC 10UF 6.3V X5R 0603; TOLERANCE: 20%; Type: capacitor; VENDOR: TDK; VPC: 6.3V; Voltage: 6.3V
C27 = PAS,CAP,NP,large: DigiKey: 445-4952-1-ND; DigiReel: 445-4952-6-ND; Family: passive; Index PN: 681; Lead Style: SMT; MFG: TDK; Material: x7r; P/D_NUM: C1005X7R1C104K050BC; Part Number: C1005X7R1C104K050BC; Part Specific: CAP CER .1UF 16V X7R 0402; TOLERANCE: 10%; Type: capacitor; VENDOR: TDK; VPC: 16V; Voltage: 25V
C32 C43 = PAS,CAP,NP,large: DigiKey: 587-3152-1-ND; DigiReel: 587-3152-2-ND; Family: passive; Index PN: 1227; Lead Style: SMT; MFG: Taiyo Yuden; Material: x5r; P/D_NUM: EMK325ABJ107MM-T; Part Number: EMK325ABJ107MM-T; Part Specific: CAP CER 100UF 16V 20% X5R 1210; TOLERANCE: 20%; Type: capacitor; VENDOR: Taiyo Yuden; VPC: 16V
C36 = PAS,CAP,NP,large: DigiKey: 445-4991-1-ND; DigiReel: 445-4991-6-ND; Family: passive; Index PN: 916; Lead Style: SMT; MFG: TDK; Material: x5r; P/D_NUM: C1005X5R1V105M050BC; Part Number: C1005X5R1V105M050BC; Part Specific: CAP CER 1.0UF 10V X5R 0402; TOLERANCE: 20%; Type: capacitor; VENDOR: TDK; VPC: 10V; Voltage: 16V
C37 = PAS,CAP,NP,large: DigiKey: 445-1262-1-ND; DigiReel: 445-1262-6-ND; Family: passive; Index PN: 908; Lead Style: SMT; MFG: Murata; Material: x7r; P/D_NUM: GRM155R71C103KA01D; Part Number: GRM155R71C103KA01D; Part Specific: CAP CER 10000PF 16V X7R 10% 0402; TOLERANCE: 10%; Type: capacitor; VENDOR: TDK; VPC: 16V; Voltage: 16V
C38 = PAS,CAP,NP,large: DigiKey: 445-4999-1-ND; DigiReel: 445-4999-6-ND; Family: passive; Index PN: 915; Lead Style: SMT; MFG: TDK; Material: x5r; P/D_NUM: C1005X5R0J225M; Part Number: C1005X5R0J225M; Part Specific: CAP CER 2.2UF 6.3V X5R 0402; TOLERANCE: 10%; Type: capacitor; VENDOR: TDK; VPC: 6.3V; Voltage: 25V
C39 = PAS,CAP,NP,large: DigiKey: 445-4978-1-ND; DigiReel: 445-4978-6-ND; Family: passive; Index PN: 917; Lead Style: SMT; MFG: TDK; Material: x5r; P/D_NUM: C1005X5R1V105K050BC; Part Number: C1005X5R1V105K050BC; Part Specific: CAP CER 1.0UF 16V X5R 0402; TOLERANCE: 10%; Type: capacitor; VENDOR: TDK; VPC: 16V; Voltage: 25V
C40 = PAS,CAP,NP,large: DigiKey: 490-3895-1-ND; DigiReel: 490-3895-6-ND; Family: passive; Index PN: 904; Lead Style: SMT; MFG: Murata; Material: y5v; P/D_NUM: GRM188F51E105ZA12D; Part Number: GRM188F51E105ZA12D; Part Specific: CAP CER 1.0UF 25V Y5V 0603; TOLERANCE: -20%,+80%; Type: capacitor; VENDOR: Murata; VPC: 25V; Voltage: 25V
C41 C129 C130 = PAS,CAP,NP,large: DigiKey: 445-4952-1-ND; DigiReel: 445-4952-6-ND; Family: passive; Index PN: 681; Lead Style: SMT; MFG: TDK; Material: x7r; P/D_NUM: C1005X7R1C104K050BC; Part Number: C1005X7R1C104K050BC; Part Specific: CAP CER .1UF 16V X7R 0402; TOLERANCE: 10%; Type: capacitor; VENDOR: TDK; VPC: 16V; Voltage: 16V
C42 = PAS,CAP,NP,large: DigiKey: 445-4972-1-ND; DigiReel: 445-4972-6-ND; Family: passive; Index PN: 923; Lead Style: SMT; MFG: Taiyo Yuden; Material: x5r; P/D_NUM: EMK105BJ224KV-F; Part Number: EMK105BJ224KV-F; Part Specific: CAP CER .22UF 16V X5R 0402; Type: capacitor; VENDOR: TDK; VPC: 16V; Voltage: 25V
C44 = PAS,CAP,NP,large: DigiKey: 445-4991-1-ND; DigiReel: 445-4991-6-ND; Family: passive; Index PN: 916; Lead Style: SMT; MFG: TDK; Material: x5r; P/D_NUM: C1005X5R1V105M050BC; Part Number: C1005X5R1V105M050BC; Part Specific: CAP CER 1.0UF 10V X5R 0402; TOLERANCE: 20%; Type: capacitor; VENDOR: TDK; VPC: 10V
C121 = PAS,CAP,NP,large: DigiKey: 445-4112-1-ND; DigiReel: 445-4112-6-ND; Family: passive; Index PN: 906; Lead Style: SMT; MFG: TDK; Material: x5r; P/D_NUM: C1608X5R0J106M080AB; Part Number: C1608X5R0J106M080AB; Part Specific: CAP CERAMIC 10UF 6.3V X5R 0603; TOLERANCE: 20%; Type: capacitor; VENDOR: TDK; VPC: 6.3V
C25 C33 C123 C126 C131-C134 = PAS,CAP,NP,large: DigiKey: 445-4952-1-ND; DigiReel: 445-4952-6-ND; Family: passive; Index PN: 681; Lead Style: SMT; MFG: TDK; Material: x7r; P/D_NUM: C1005X7R1C104K050BC; Part Number: C1005X7R1C104K050BC; Part Specific: CAP CER .1UF 16V X7R 0402; TOLERANCE: 10%; Type: capacitor; VENDOR: TDK; VPC: 16V
D1 = PAS,DIODE,SCHOTTKY,large: DigiKey: 568-4131-1-ND; DigiReel: 568-4131-6-ND; Family: passive; Index PN: 907; Lead Style: SMT; MFG: NXP Semiconductors; P/D_NUM: PMEG4002EL,315; Part Number: PMEG4002EL,315; Part Specific: SCHOTTKY RECT 40V 0.2A SOD882; Type: diode,schottky; VENDOR: NXP Semiconductors; VPC: 40V; Voltage: 40V
F100 F101 = PAS,FERRITE_BEAD,3: DigiKey: 490-5202-1-ND; DigiReel: 490-5202-6-ND; Family: passive; Install: Y; Lead Style: SMT; MFG: Murata; Part Specific: FERRITE CHIP 80 OHM 1500MA 0402; Type: ferrite bead; VENDOR: Murata; VPC: 1500mA
J2 = EM,CONN,PWRJACK,RAPC712X_0: DigiKey: CP-002A-ND; DigiReel: ---; Family: electro/mechanical; Index PN: --; Lead Style: TH; MFG: CUI Inc.; Part Specific: CONN POWERJACK 2.1mm; Type: connector; Vendor: CUI Inc.
J3-J5 = EM,HDR,2P,1R,2x: DigiKey: SAM1029-02-ND; DigiReel: ---; Family: electro/mechanical; Index PN: 180; Install: Y; Lead Style: TH; MFG: Samtec; P/D_NUM: TSW-102-07-G-S; Part Number: TSW-102-07-G-S; Part Specific: CONN HEADER 2POS .100in. SGL GOLD; Pin Cnt: 2; Pin Spacing: 100mil; Row Cnt: 1; Type: header; VENDOR: Samtec
JLEDFLEX = EM,CONN,10P,ZIF: MFG: Molex; Part Number: MT46H32M16LFBF-5 IT:C; Part Specific: LED FLEX CONNECTOR
L1 L2 = PAS,INDUCTOR,_large: DigiKey: 490-5114-1-ND; DigiReel: 490-5114-6-ND; Family: passive; Index PN: 1149; Install: Y; Lead Style: SMT; MFG: Murata; P/D_NUM: LQM2HPN2R2MG0L; Part Number: LQM2HPN2R2MG0L; Part Specific: INDUCTOR 2.2UH 20% 1300MA 1008; Type: inductor; VENDOR: Murata
L3 = PAS,INDUCTOR,_large: DigiKey: ---; DigiReel: ---; Family: passive; Index PN: 900; Lead Style: SMT; MFG: Coilcraft; P/D_NUM: LPS3015-222ML; Part Number: LPS3015-222ML; Part Specific: Compact, low profile shielded power inductor; Type: inductor; VENDOR: Coilcraft; VPC: 2.0A
L4 = PAS,INDUCTOR,_large: DigiKey: 587-1632-1-ND; DigiReel: 587-1632-6-ND; Family: passive; Index PN: 901; Lead Style: SMT; MFG: Taiyo Yuden; P/D_NUM: CBL2012T100M; Part Number: CBL2012T100M; Part Specific: INDUCTOR 10UH 20% 0805 SMD; Type: inductor; VENDOR: Taiyo Yuden
R1 = PAS,R,large: DigiKey: P120KLCT-ND; DigiReel: P120KLDKR-ND; Family: passive; Lead Style: SMT; MFG: Panasonic; Material: chip; P/D_NUM: ERJ-2RKF1203X; Part Number: ERJ-2RKF1203X; Part Specific: RES SMD 120K OHM 1% 1/10W 0402; TOLERANCE: 1%; Type: resistor; VENDOR: Panasonic; VPC: 1/10W
R2 = PAS,R,large: DigiKey: 311-82.0KLRCT-ND; DigiReel: 311-82.0KLRDKR-ND; Family: passive; Lead Style: SMT; MFG: Yageo; P/D_NUM: RC0402FR-0782KL; Part Number: RC0402FR-0782KL; Part Specific: RES 82K OHM 1/16W 1% 0402 SMD; TOLERANCE: 1%; Type: resistor; VENDOR: Yageo; VPC: 1/16W
R83 = PAS,R,large: DigiKey: 311-180KLRCT-ND; DigiReel: 311-180KLRDKR-ND; Family: passive; Index PN: 1179; Lead Style: SMT; MFG: Yageo; P/D_NUM: RC0402FR-07180KL; Part Number: RC0402FR-07180KL; Part Specific: RES 180K OHM 1/16W 1% 0402 SMD; TOLERANCE: 1%; Type: resistor; VENDOR: Yageo; VPC: 1/16W
R84 = PAS,R,large: DigiKey: 311-360KLRCT-ND; DigiReel: 311-360KLRDKR-ND; Family: passive; Index PN: 1180; Lead Style: SMT; MFG: Yageo; P/D_NUM: RC0402FR-07360KL; Part Number: RC0402FR-07360KL; Part Specific: RES 360K OHM 1/16W 1% 0402 SMD; TOLERANCE: 1%; Type: resistor; VENDOR: Yageo; VPC: 1/16W
R89 = PAS,R,large: DigiKey: P30.0KLCT-ND; DigiReel: P30.0KLDKR-ND; Family: passive; Index PN: 909; Lead Style: SMT; MFG: Panasonic; Material: chip; P/D_NUM: ERJ-2RKF3002X; Part Number: ERJ-2RKF3002X; Part Specific: RES 30.0K OHM 1/10W 1% 0402 SMD; Power: 1/16W; Tolerance: 1%; Type: resistor; VPC: 1/16W; Vendor: Panasonic
R90 R91 R96 R103 R117 R120 R128 = PAS,R,large: DigiKey: P0.0JCT-ND; DigiReel: P0.0JDKR-ND; Family: passive; Index PN: 687; Lead Style: SMT; MFG: Panasonic; Material: chip; P/D_NUM: ERJ-2GE0R00X; Part Number: ERJ-2GE0R00X; Part Specific: RES 0.0 OHM 1/16W 0402 SMD; Power: 1/16W; Type: resistor; VPC: 1/16W; Vendor: Panasonic
R92 = PAS,R,large: DigiKey: 408-1420-1-ND; DigiReel: 408-1420-6-ND; Family: passive; Index PN: 912; Lead Style: SMT; MFG: Susumu; Material: chip; P/D_NUM: RL0816S-R10-F; Part Number: RL0816S-R10-F; Part Specific: RES HP .10 OHM 1/5W 1% 0603 SMD; Power: 1/5W; Tolerance: 1%; Type: resistor; VPC: 1/5W; Vendor: Susumu
R70 R93 = PAS,R,large: DigiKey: 541-100KLCT-ND; DigiReel: 541-100KLDKR-ND; Family: passive; Index PN: 712; Lead Style: SMT; MFG: Vishay/Dale; Material: chip; P/D_NUM: CRCW0402100KFKED; Part Number: CRCW0402100KFKED; Part Specific: RES 100K OHM 1/10W 1% 0402 SMD; Power: 1/16W; TOLERANCE: 1%; Type: resistor; VPC: 1/16W; Vendor: Vishay/Dale
R94 = PAS,R,large: DigiKey: P887KLCT-ND; DigiReel: P887KLDKR-ND; Family: passive; Index PN: 924; Lead Style: SMT; MFG: Panasonic; Material: chip; P/D_NUM: ERJ-2RKF8873X; Part Number: ERJ-2RKF8873X; Part Specific: RES 887K OHM 1/16W 1% 0402 SMD; Power: 1/16W; TOLERANCE: 1%; Type: resistor; VENDOR: Panasonic; VPC: 1/16W
R95 = PAS,R,large: DigiKey: P953KLCT-ND; DigiReel: P953KLDKR-ND; Family: passive; Index PN: 969; Lead Style: SMT; MFG: Panasonic; Material: chip; P/D_NUM: ERJ-2RKF9533X; Part Number: ERJ-2RKF9533X; Part Specific: RES 953K OHM 1/10W 1% 0402 SMD; TOLERANCE: 1%; Type: resistor; VENDOR: Panasonic; VPC: 1/16W
R74 R104 R108-R112 R116 = PAS,R,large: DigiKey: 541-100KLCT-ND; DigiReel: 541-100KLDKR-ND; Family: passive; Index PN: 712; Lead Style: SMT; MFG: Vishay/Dale; Material: chip; P/D_NUM: CRCW0402100KFKED; Part Number: CRCW0402100KFKED; Part Specific: RES 100K OHM 1/10W 1% 0402 SMD; Power: 1/16W; TOLERANCE: 1%; Type: resistor; VENDOR: Vishay/Dale; VPC: 1/16W
R124 = PAS,R,large: DigiKey: P200ACT-ND; DigiReel: P200ADKR-ND; Family: passive; Index PN: 1242; Install: Y; Lead Style: SMT; MFG: Panasonic; P/D_NUM: ERJ-6GEYJ201V; Part Number: ERJ-6GEYJ201V; Part Specific: RES 200 OHM 1/8W 5% 0805 SMD; Power: 1/8W; Type: resistor; VENDOR: Panasonic; VPC: 1/8W
RT1 = PAS,THERMISTOR,large: DigiKey: 490-4803-1-ND; DigiReel: 490-4803-6-ND; Family: passive; Index PN: 910; Lead Style: SMT; MFG: Murata; P/D_NUM: NCP15WF104F03RC; Part Number: NCP15WF104F03RC; Part Specific: THERMISTOR 100K OHM NTC 0402 SMD; TOLERANCE: 1%; Type: thermistor; VENDOR: Murata
TP1 TP3-TP15 TP19-TP22 TP24-TP27 TP32 TP33 = EM,TERM,TESTPOINT: Family: board feature; Index PN: 1145; Install: DNI; Lead Style: SMT; MFG: -- NOT A PART --; Part Number: -- NOT A PART --; Part Specific: Not a Part; Type: pad pattern; Vendor: -- NOT A PART --
TP2 TP16-TP18 TP23 TP28-TP31 TP34 = EM,TERM,TESTPOINT: Family: board feature; Index PN: 122; Install: DNI; MFG: -- NOT A PART --; Part Number: -- NOT A PART --; Part Specific: Not a Part; Type: hole,plated; Vendor: -- NOT A PART --
U1 U2 = PWR,REG,TPS62260,TSOT23_DDC: DigiKey: 296-22469-1-ND; DigiReel: 296-22469-6-ND; Family: power; Index PN: 1147; Install: Y; Lead Style: SMT; MFG: Texas Instruments; Part Specific: IC REG BUCK SYNC ADJ TSOT23-5; Type: regulator; Vendor: Texas Instruments
U5 = TIDLP,PAD1000_0: MFG: Texas Instruments; Part Number: DLPS1000PT; Part Specific: DLPA1000 PMIC LED DRIVER; Vendor: Texas Instruments
U7 = TPS71501DCK: Install: Y; MFG: Texas Instruments; Part Specific: REGULATOR; Type: Regulator
D2 D3 = PAS,DIODE,LED,large_0: DigiKey: 67-1357-1-ND; DigiReel: 67-1357-6-ND; Family: passive; Index PN: 31; Install: Y; Lead Style: SMT; MFG: Lumex; P/D_NUM: SML-LX1206GC-TR; Part Number: SML-LX1206GC-TR; Part Specific: LED 565NM WTR CLR GREEN 1206 SMD; Type: diode,led; VENDOR: Lumex
P1 P2 = EM,HDR,46P,2R,2x: MFG: Major League Electronics; P/D_NUM: SSHQ-123-D-08-67-LF; Part Number: SSHQ-123-D-08-67-LF; Part Specific: 46-PIN MALE FEMALE HEADERS; Type: Header; VENDOR: Future Electronics
R23 R71 R97 = PAS,R,large: DigiKey: P10.0KLCT-ND; DigiReel: P10.0KLDKR-ND; Family: passive; Index PN: 680; Lead Style: SMT; MFG: Panasonic; Material: chip; P/D_NUM: ERJ-2RKF1002X; Part Number: ERJ-2RKF1002X; Part Specific: RES 10k OHM 1% 1/10W 0402 SMD; Power: 1/16W; TOLERANCE: 1%; Type: resistor; VENDOR: Panasonic; VPC: 1/16W
R118 R119 = PAS,R,large: DigiKey: 311-5.6KJRCT-ND; DigiReel: 311-5.6KJRDKR-ND; Family: Passive; MFG: Yageo; Material: chip; P/D_NUM: RC0402JR-075K6L; Part Number: RC0402JR-075K6L; Part Specific: RES 5.6K OHM 5% 1/16W 0402 SMD; TOLERANCE: 5%; Type: Resistor; VENDOR: Yageo; VPC: 1/16W
R121-R123 = PAS,R,large: DigiKey: P4.75KLCT-ND; DigiReel: P4.75KLDKR-ND; Family: Passive; MFG: Panasonic; Material: chip; P/D_NUM: ERJ-2RKF4751X; Part Number: ERJ-2RKF4751X; Part Specific: RES 4.75K OHM 1% 1/10W 0402 SMD; TOLERANCE: 1%; Type: Resistor; VENDOR: Panasonic
R125 = PAS,R,large: DigiKey: P1.00KLCT-ND; DigiReel: P1.00KLDKR-ND; Family: Passive; MFG: Panasonic; Material: chip; P/D_NUM: ERJ-2RKF1001X; Part Number: ERJ-2RKF4751X; Part Specific: RES 4.75K OHM 1% 1/10W 0402 SMD; TOLERANCE: 1%; Type: resistor; VENDOR: Panasonic
R126 R129 = PAS,R,large: DigiKey: P100LCT-ND; DigiReel: P100LDKR-ND; Family: passive; Index PN: 690; Lead Style: SMT; MFG: Panasonic; Material: chip; P/D_NUM: ERJ-2RKF1000X; Part Number: ERJ-2RKF1000X; Part Specific: RES 100 OHM 1/10W 1% 0402 SMD; Power: 1/16W; TOLERANCE: 1%; Type: resistor; VENDOR: Panasonic; VPC: 1/16W
U4 = MEM,EEPROM,CAT24C256: MFG: ON Semiconductor; Part Specific: Onboard EEPROM
U6 = LOG,BUF,SN74LVC1G125DCK: Install: Y; MFG: Texas Instruments; Part Specific: BUFFER; Type: Buffer
U8 = LOG,INV,OPENDRN,SN74AUP1G06DCK: MFG: Texas Instruments; Part Number: SN74AUP1G06DCK; Part Specific: INVERTER BUFFER; Type: Inverter Buffer
U9 = PWR,MON,TLV809I50: Install: Y; MFG: Texas Instruments; Part Number: TLV809I50DBZT; Part Specific: VOLTAGE SUPERVISOR; Type: Voltage Supervisor; Vendor: Texas Instruments
U10 = LOG,SN74LVC1G3208_2: MFG: Texas Instruments; Part Number: SN74LVC1G3208DCKR; Part Specific: OR-AND LOGIC IC; Type: OR_AND Logic IC
U11 = PWR,SW,TPS22929DDBV: DigiKey: 296-30174-1-ND; DigiReel: 296-30174-6-ND; Family: power; Lead Style: SMT; MFG: Texas Instruments; Part Specific: IC LOAD SWITCH SOT23-6; Type: switch; Vendor: Texas Instruments
C111 = PAS,CAP,NP,large: DigiKey: 445-1238-1-ND; DigiReel: 445-1238-6-ND; Family: passive; Index PN: 960; Install: Y; Lead Style: SMT; MFG: Murata; Material: npo; P/D_NUM: GRM1555C1H180JA01D; Part Number: GRM1555C1H180JA01D; Part Specific: CAP CER 18PF 50V C0G 5% 0402; Type: capacitor; VENDOR: TDK; VPC: 50V
C122 = PAS,CAP,NP,large: DigiKey: 445-1238-1-ND; DigiReel: 445-1238-6-ND; Family: passive; Index PN: 960; Lead Style: SMT; MFG: Murata; Material: npo; P/D_NUM: GRM1555C1H180JA01D; Part Number: GRM1555C1H180JA01D; Part Specific: CAP CER 18PF 50V C0G 5% 0402; Type: capacitor; VENDOR: TDK; VPC: 50V
R72 R75-R78 = PAS,R,large: DigiKey: P30.1LCT-ND; DigiReel: P30.1LDKR-ND; Family: passive; Index PN: 976; Lead Style: SMT; MFG: Panasonic; Material: chip; P/D_NUM: ERJ-2RKF30R1X; Part Number: ERJ-2RKF30R1X; Part Specific: RES 30.1 OHM 1/16W 1% 0402 SMD; Power: 1/16W; TOLERANCE: 1%; Type: resistor; VENDOR: Panasonic; VPC: 1/16W
R85-R87 = PAS,R,large: DigiKey: P1.00KLCT-ND; DigiReel: P1.00KLDKR-ND; Family: Passive; MFG: Panasonic; Material: chip; P/D_NUM: ERJ-2RKF1001X; Part Number: ERJ-2RKF1001X; Part Specific: RES 1k OHM 1% 1/10W 0402 SMD; TOLERANCE: 1%; Type: resistor; VENDOR: Panasonic
R101 = PAS,R,large: DigiKey: P953KLCT-ND; DigiReel: P953KLDKR-ND; Family: passive; Index PN: 969; Install: Y; Lead Style: SMT; MFG: Panasonic; Material: chip; P/D_NUM: ERJ-2RKF9533X; Part Number: ERJ-2RKF9533X; Part Specific: RES 953K OHM 1/10W 1% 0402 SMD; TOLERANCE: 1%; Type: resistor; VENDOR: Panasonic; VPC: 1/16W
R102 = PAS,R,large: DigiKey: P100LCT-ND; DigiReel: P100LDKR-ND; Family: passive; Index PN: 690; Install: Y; Lead Style: SMT; MFG: Panasonic; Material: chip; P/D_NUM: ERJ-2RKF1000X; Part Number: ERJ-2RKF1000X; Part Specific: RES 100 OHM 1/10W 1% 0402 SMD; Power: 1/16W; TOLERANCE: 1%; Type: resistor; VENDOR: Panasonic; VPC: 1/16W
TPGND1 TPGND2 = EM,TERM,TESTPOINT: DigiKey: ---; DigiReel: ---; Family: board feature; Index PN: 995; Install: DNI; MFG: -- NOT A PART --; Part Number: -- NOT A PART --; Part Specific: Not a Part; Type: hole,plated; Vendor: -- NOT A PART --
U3 = W25Q16DW: DigiKey Part Number: W25Q16DWSSIG-ND; Install: Y; MFG: Winbond; P/D_NUM: W25Q16DWSSIG; Part Number: W25Q16DWSSIG; Part Specific: Flash Memory; Type: Flash Memory; Vendor: Winbond
U12 = TIDLP,DPP2607: DigiKey: ---; Family: processor; Index PN: 1374; Lead Style: SMT; MFG: Texas Instruments; P/D_NUM: 2510465-0001; Part Number: 2510465-0001; Part Specific: DLPC2607 CONTROLLER; Type: dlp; Vendor: Texas Instruments
XD100 = XTAL_NX3225GA: DigiKey Part Number: 887-2368-1-ND; DigiReel: 887-2368-6-ND; Install: Y; MFG: NDK; P/D_NUM: 7M-16.666670MAAE-T; Part Number: 7M-16.666670MAAE-T; Part Specific: 16.667 MHZ CRYSTAL; VENDOR: TXC Corp
C3-C6 C10 C15-C17 = PAS,CAP,NP,large: DigiKey: 445-15903-1-ND; DigiReel: 445-15903-6-ND; Family: passive; Lead Style: SMT; MFG: TDK; Material: x7r; P/D_NUM: C0603X6S1C104K030BC; Part Number: C0603X6S1C104K030BC; Part Specific: CAP CER .1UF 16V X6S 0201; TOLERANCE: 10%; Type: capacitor; VENDOR: TDK; VPC: 16V
C7 = PAS,CAP,NP,large: DigiKey: 490-13226-1-ND; DigiReel: 490-13226-6-ND; Family: passive; Lead Style: SMT; MFG: Murata; Material: x5r; P/D_NUM: GRM033R61A105ME15D; Part Number: GRM033R61A105ME15D; Part Specific: CAP CER 1.0UF 10V X5R 0201; TOLERANCE: 20%; Type: capacitor; VENDOR: Murata; VPC: 10V
R3 R5-R22 R24-R57 R59-R66 R79-R82 R100 = PAS,R,large: DigiKey: P30AGCT-ND; DigiReel: P30AGDKR-ND; Family: passive; Index PN: 996; Lead Style: SMT; MFG: Panasonic; Material: chip; P/D_NUM: ERJ-1GEJ300C; Part Number: ERJ-1GEJ300C; Part Specific: RES 30 OHM 1/20W 5% 0201 SMD; Power: 1/20W; TOLERANCE: 5%; Type: resistor; VENDOR: Panasonic; VPC: 1/20W
R58 = PAS,R,large: DigiKey: P10.0KABDKR-ND; DigiReel: P10.0KABDKR-ND; Family: passive; Install: DNI; Lead Style: SMT; MFG: Panasonic; Material: chip; P/D_NUM: ERJ-1GEF1002C; Part Number: ERJ-1GEF1002C; Part Specific: RES 10k OHM 1/20W 1% 0201 SMD; Power: 1/20W; TOLERANCE: 1%; Type: resistor; VPC: 1/20W; Vendor: Panasonic
R67 = PAS,R,large: DigiKey: P100ABDKR-ND; DigiReel: P100ABDKR-ND; Family: passive; Lead Style: SMT; MFG: Panasonic; Material: chip; P/D_NUM: ERJ-1GEF1000C; Part Number: ERJ-1GEF1000C; Part Specific: RES 100 OHM 1/20W 1% 0201 SMD; Power: 1/20W; TOLERANCE: 1%; Type: resistor; VENDOR: Panasonic; VPC: 1/20W
U13 = MEM,SDRAM,64x16,BGA_60P: DigiKey: 557-1627-ND; Install: Y; MFG: Micron Technology Inc.; P/D_NUM: MT46H32M16LFBF-5 IT:C; Part Number: MT46H32M16LFBF-5 IT:C; Part Specific: IC SDRAM 512MBIT 200MHZ 60BGA
C124 C125 C127 = PAS,CAP,NP,large: DigiKey: 587-1456-1-ND; DigiReel: 587-1456-6-ND; Family: passive; Index PN: 922; Lead Style: SMT; MFG: Taiyo Yuden; Material: x5r; P/D_NUM: TMK105BJ104KV-F; Part Number: TMK105BJ104KV-F; Part Specific: CAP CER .10UF 25V X5R 0402; Type: capacitor; VENDOR: Taiyo Yuden; VPC: 25V
C128 = PAS,CAP,NP,large: DigiKey: 445-5191-1-ND; DigiReel: 445-5191-6-ND; Family: passive; Index PN: 913; Lead Style: SMT; MFG: KEMET; Material: x7r; P/D_NUM: C0603X224K3RAC7867; Part Number: C0603X224K3RAC7867; Part Specific: CAP CER 0.22UF 25V 10% X7R 0603; TOLERANCE: 10%; Type: capacitor; VENDOR: TDK; VPC: 25V
J1 = EM,CONN,50P,2R,90deg_0: MFG: ACES Electronics; Part Number: 50028-05081-001; Part Specific: DMD _Connector; Pin Cnt: 50; Type: Connector; VENDOR: ACES Electronics
R68 R69 R107 = PAS,R,large: DigiKey: P0.0JCT-ND; DigiReel: P0.0JDKR-ND; Family: passive; Index PN: 687; Install: Y; Lead Style: SMT; MFG: Panasonic; Material: chip; P/D_NUM: ERJ-2GE0R00X; Part Number: ERJ-2GE0R00X; Part Specific: RES 0.0 OHM 1/16W 0402 SMD; Power: 1/16W; Type: resistor; VPC: 1/16W; Vendor: Panasonic
R105 R106 R113-R115 = PAS,R,large: DigiKey: P0.0JCT-ND; DigiReel: P0.0JDKR-ND; Family: passive; Index PN: 687; Install: DNI; Lead Style: SMT; MFG: Panasonic; Material: chip; P/D_NUM: ERJ-2GE0R00X; Part Number: ERJ-2GE0R00X; Part Specific: RES 0.0 OHM 1/16W 0402 SMD; Power: 1/16W; Type: resistor; VPC: 1/16W; Vendor: Panasonic

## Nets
DGND: C1.1(P) C2.2(N) C3.2(N) C4.2(N) C5.2(N) C6.2(N) C7.2(N) C8.1(P) C9.1(P) C10.2(N) C11.1(P) C12.1(P) C13.2(N) C14.2(N) C15.2(N) C16.2(N) C17.2(N) C18.1(P) C19.1(P) C20.1(P) C21.1(P) C23.1(P) C24.2(N) C25.2(N) C26.2(N) C27.1(P) C28.2(N) C29.2(N) C30.2(N) C31.2(N) C32.2(N) C33.2(N) C34.2(N) C35.2(N) C36.1(P) C37.2(N) C38.2(N) C39.2(N) C40.2(N) C41.2(N) C42.2(N) C43.2(N) C44.2(N) C100.2(N) C101.2(N) C102.2(N) C103.2(N) C104.2(N) C105.2(N) C106.2(N) C107.2(N) C108.2(N) C109.2(N) C110.2(N) C111.1(P) C112.2(N) C113.2(N) C114.2(N) C115.2(N) C116.2(N) C117.2(N) C118.2(N) C119.2(N) C122.2(N) C123.2(N) C124.2(N) C125.2(N) C126.2(N) C127.2(N) C128.2(N) C129.2(N) C130.2(N) C131.2(N) C132.2(N) C133.2(N) C134.2(N) D3.1(P1) F100.2(N2) J1.5(P5) J1.6(P6) J1.9(P9) J1.10(P10) J1.15(P15) J1.18(P18) J1.25(P25) J1.28(P28) J1.33(P33) J1.34(P34) J1.36(P36) J1.37(P37) J1.38(P38) J1.45(P45) J1.49(P49) J1.50(P50) J1.51(P51) J1.52(P52) J2.2(SLEEVE) J3.2 J4.1 J5.1 JLEDFLEX.6(P6) P1.1(P1) P1.2(P2) P2.1(P1) P2.2(P2) P2.44(P44) P2.45(P45) P2.46(P46) R1.2(N2) R23.1(N1) R58.1(N1) R72.2(N2) R74.1(N1) R83.2(N2) R92.2(N2) R94.1(N1) R100.2(N2) R111.1(N1) R112.1(N1) RT1.2 TP1.1(P1) TP14.1(P1) TPGND1.1(P1) TPGND2.1(P1) U1.2(GND) U2.2(GND) U3.4(GND) U4.4(GND) U5.A3(AGND1) U5.A6(PGNDR) U5.C1(PGNDL_1) U5.C2(PGNDL_2) U5.D6(DGND) U5.D7(AGND) U6.1(OEZ) U6.3(GND) U7.2(GND) U8.3(GND) U9.1(GND) U10.2(GND) U11.2(GND) U11.5(GND) U12.D4(VSS) U12.D7(VSS) U12.D10(VSS) U12.D12(VSS) U12.G4(VSS) U12.G12(VSS) U12.H4(VSS) U12.K4(VSS) U12.L12(VSS) U12.M4(VSS) U12.M7(VSS) U12.M10(VSS) U13.A1(VSS) U13.A3(VSSQ) U13.B9(VSSQ) U13.C1(VSSQ) U13.D9(TEST) U13.E1(VSSQ) U13.F1(VSS) U13.K1(VSS)
V2V5: C38.1(P) U5.E7(V2V5)
V6V: C27.2(N) U5.F1(V6V)
VDD_PLL: C120.1(P) C121.2(N) F101.2(N2) U12.H12(VDD_PLL)
VINA: C36.2(N) R117.2(N2) U5.G4(VINA)
VINTF: C118.1(P) C119.1(P) C131.1(P) P2.3(P3) R118.2(N2) R119.2(N2) R120.2(N2) R121.2(N2) R122.2(N2) R123.2(N2) TP34.1(P1) U4.8(VCC) U11.1(VOUT) U12.D11(VCC_INTF) U12.E12(VCC_INTF)
VSS_PLL: C120.2(N) C121.1(P) F100.1(N1) U12.J13(VSS_PLL)
B[0]: P1.19(P19) U12.G14(PDATA_0)
B[1]: P1.17(P17) U12.G13(PDATA_1)
B[2]: P1.16(P16) U12.F15(PDATA_2)
B[3]: P1.34(P34) U12.F14(PDATA_3)
B[4]: P1.35(P35) U12.F13(PDATA_4)
B[5]: P1.33(P33) U12.E15(PDATA_5)
B[6]: P1.31(P31) U12.E14(PDATA_6)
B[7]: P1.32(P32) U12.E13(PDATA_7)
BLU_CATHODE: JLEDFLEX.9(P9) JLEDFLEX.10(P10) TP31.1(P1) U5.G7(SW6)
CMP_OUT: R74.2(N2) U5.D4(CMP_OUT) U12.A6(CMP_OUT)
CMP_PWM_F: C25.1(P) R85.2(N2) R86.1(N1)
CMP_PWM_F2: C33.1(P) R86.2(N2) R87.1(N1)
CMP_PWR: R89.2(N2) U12.P5(GPIO0_CMPPWR)
DATEN: P1.30(P30) U12.G15(DATEN_CMD)
DBIC_CSZ: R71.1(N1) U12.B10(DBIC_CSZ)
DMD_BUS: J1.27(P27) R37.1(N1)
DMD_BUS_T: R37.2(N2) U12.L13(DMD_DAD_BUS)
DMD_D0: J1.26(P26) R11.1(N1)
DMD_D0_T: R11.2(N2) U12.M15(DMD_D0)
DMD_D1: J1.4(P4) R6.1(N1)
DMD_D1_T: R6.2(N2) U12.N14(DMD_D1)
DMD_D2: J1.8(P8) R7.1(N1)
DMD_D2_T: R7.2(N2) U12.M14(DMD_D2)
DMD_D3: J1.12(P12) R10.1(N1)
DMD_D3_T: R10.2(N2) U12.N15(DMD_D3)
DMD_D4: J1.14(P14) R13.1(N1)
DMD_D4_T: R13.2(N2) U12.P13(DMD_D4)
DMD_D5: J1.16(P16) R5.1(N1)
DMD_D5_T: R5.2(N2) U12.P14(DMD_D5)
DMD_D6: J1.24(P24) R9.1(N1)
DMD_D6_T: R9.2(N2) U12.P15(DMD_D6)
DMD_D7: J1.20(P20) R8.1(N1)
DMD_D7_T: R8.2(N2) U12.R15(DMD_D7)
DMD_D8: J1.7(P7) R16.1(N1)
DMD_D8_T: R16.2(N2) U12.R12(DMD_D8)
DMD_D9: J1.3(P3) R19.1(N1)
DMD_D9_T: R19.2(N2) U12.N11(DMD_D9)
DMD_D10: J1.13(P13) R17.1(N1)
DMD_D10_T: R17.2(N2) U12.P11(DMD_D10)
DMD_D11: J1.11(P11) R18.1(N1)
DMD_D11_T: R18.2(N2) U12.R11(DMD_D11)
DMD_D12: R22.1(N1) R105.2(N2)
DMD_D12_OPT: J1.44(P44) R105.1(N1)
DMD_D12_T: R22.2(N2) U12.N10(DMD_D12)
DMD_D13: R21.1(N1) R106.2(N2)
DMD_D13_OPT: J1.46(P46) R106.1(N1)
DMD_D13_T: R21.2(N2) U12.P10(DMD_D13)
DMD_D14: R20.1(N1) R113.2(N2)
DMD_D14_OPT: J1.48(P48) R113.1(N1)
DMD_D14_T: R20.2(N2) U12.R10(DMD_D14)
DMD_DCLK: J1.17(P17) R3.1(N1)
DMD_DCLK_T: R3.2(N2) U12.N13(DMD_DCLK)
DMD_LOADB: J1.19(P19) R14.1(N1) R109.1(N1)
DMD_LOADB_T: R14.2(N2) U12.R13(DMD_LOADB)
DMD_OEZ: J1.35(P35) R108.1(N1) U12.M13(DMD_DAD_OEZ)
DMD_SAC_BUS: J1.31(P31) R38.1(N1)
DMD_SAC_BUS_T: R38.2(N2) U12.L15(DMD_SAC_BUS)
DMD_SAC_CLK: R36.1(N1) R114.1(N1)
DMD_SAC_CLK_OPT: J1.43(P43) R114.2(N2)
DMD_SAC_CLK_T: R36.2(N2) U12.L14(DMD_SAC_CLK)
DMD_SCTRL: J1.23(P23) R12.1(N1)
DMD_SCTRL_T: R12.2(N2) U12.R14(DMD_SCTRL)
DMD_STRB: J1.30(P30) R39.1(N1)
DMD_STRB_T: R39.2(N2) U12.K13(DMD_DAD_STRB)
DMD_TRC: R15.1(N1) R115.1(N1)
DMD_TRC_OPT: J1.47(P47) R115.2(N2)
DMD_TRC_T: R15.2(N2) U12.P12(DMD_TRC)
DMD_VBIAS: C124.1(P) J1.32(P32) R68.2(N2) TP17.1(P1)
DMD_VOFS: C127.1(P) J1.29(P29) R107.2(N2) TP16.1(P1)
DMD_VRST: C125.1(P) J1.40(P40) R69.2(N2) TP18.1(P1)
DPP_CMP_PWM: R85.1(N1) U12.B7(CMP_PWM)
DPP_PLLI: C111.2(N) R101.1(N1) U12.K15(PLL_REFCLK_I) XD100.3(N)
DPP_PLLO: R101.2(N2) R102.1(N1) U12.J15(PLL_REFCLK_O)
DPP_SPICLK: R78.2(N2) U12.A4(SPICLK)
DPP_SPICSZ0: R76.2(N2) U12.A5(SPICSZ0)
DPP_SPICSZ1: R75.2(N2) U12.C6(SPICSZ1)
DPP_SPIDOUT: R77.2(N2) U12.C5(SPIDOUT)
FLEX_TP: JLEDFLEX.5(P5) TP26.1(P1)
FLSH_1P8V: C123.1(P) R103.2(N2) U3.3(/WP) U3.7(/HOLD) U3.8(VCC)
G[0]: P1.13(P13) U12.D15(PDATA_8)
G[1]: P1.12(P12) U12.D14(PDATA_9)
G[2]: P1.42(P42) U12.C15(PDATA_10)
G[3]: P1.39(P39) U12.C14(PDATA_11)
G[4]: P1.40(P40) U12.C13(PDATA_12)
G[5]: P1.37(P37) U12.B15(PDATA_13)
G[6]: P1.38(P38) U12.B14(PDATA_14)
G[7]: P1.36(P36) U12.A15(PDATA_15)
GPIO1_RPWM: TP7.1(P1) U12.N8(GPIO1_RPWM)
GPIO2_GPWM: TP5.1(P1) U12.P9(GPIO2_GPWM)
GPIO3_BPWM: TP4.1(P1) U12.R8(GPIO3_BPWM)
GPIO4: P1.26(P26) U8.2(A) U12.C9(GPIO4_INTF)
GPIO5: P1.18(P18) U12.B9(GPIO5_INTF)
GRN_CATHODE: JLEDFLEX.7(P7) JLEDFLEX.8(P8) TP30.1(P1) U5.G6(SW5)
HOST_PRESENTZ: P2.43(P43) R97.1(N1) U10.3(B) U11.3(ON)
HSYNC: P1.29(P29) U12.H13(HSYNC_CS)
HWTEST_EN: R72.1(N1) U12.A9(HWTEST_EN)
JTAG_TCK: TP13.1(P1) U12.N5(JTAGTCK)
JTAG_TDI: TP11.1(P1) U12.P6(JTAGTDI)
JTAG_TDO: TP8.1(P1) U12.R7(JTAGTDO)
JTAG_TMS: TP10.1(P1) U12.N7(JTAGTMS)
JTAGTRSTZ: R23.2(N2) TP12.1(P1) U12.P8(JTAGTRSTZ)
L1: L3.2 U5.B1(L1_1) U5.B2(L1_2)
L2: L3.1 U5.D1(L2_1) U5.D2(L2_2)
LED_ANODE: C26.1(P) C34.1(P) C35.1(P) JLEDFLEX.1(P1) JLEDFLEX.2(P2) TP28.1(P1) U5.E1(VLED_1) U5.E2(VLED_2) U5.F2(VLED_3) U5.G1(SW1) U5.G2(SW2) U5.G3(SW3)
LED_ENABLE: R70.2(N2) U12.A11(LED_ENABLE)
LED_SEL_0: U5.F3(LED_SEL0) U12.R6(LED_SEL_0)
LED_SEL_1: U5.E3(LED_SEL1) U12.N6(LED_SEL_1)
LEDDRV_ON: TP9.1(P1) U12.P7(LEDDRV_ON)
MEM0_A0: R31.1(N1) U13.J8(A0)
MEM0_A1: R30.1(N1) U13.J9(A1)
MEM0_A2: R26.1(N1) U13.K7(A2)
MEM0_A3: R25.1(N1) U13.K8(A3)
MEM0_A4: R79.1(N1) U13.K2(A4)
MEM0_A5: R59.1(N1) U13.K3(A5)
MEM0_A6: R80.1(N1) U13.J1(A6)
MEM0_A7: R64.1(N1) U13.J2(A7)
MEM0_A8: R62.1(N1) U13.J3(A8)
MEM0_A9: R81.1(N1) U13.H1(A9)
MEM0_A10: R32.1(N1) U13.J7(A10)
MEM0_A11: R82.1(N1) U13.H2(A11)
MEM0_A12: R63.1(N1) U13.H3(A12)
MEM0_A13: R100.1(N1) U13.F7(A13)
MEM0_BA0: R40.1(N1) U13.H8(BA0)
MEM0_BA1: R27.1(N1) U13.H9(BA1)
MEM0_CASZ: R24.1(N1) U13.G8(~{CAS})
MEM0_CKE: R57.1(N1) U13.G1(CKE)
MEM0_CLK_N: R55.1(N1) R67.1(N1) U13.G3(~{CK})
MEM0_CLK_P: R56.1(N1) R67.2(N2) U13.G2(CK)
MEM0_CSZ: R28.1(N1) U13.H7(~{CS})
MEM0_DQ0: R35.1(N1) U12.N1(MEM0_DQ0)
MEM0_DQ1: R50.1(N1) U12.M2(MEM0_DQ1)
MEM0_DQ2: R33.1(N1) U12.M1(MEM0_DQ2)
MEM0_DQ3: R46.1(N1) U12.L3(MEM0_DQ3)
MEM0_DQ4: R51.1(N1) U12.L2(MEM0_DQ4)
MEM0_DQ5: R47.1(N1) U12.K2(MEM0_DQ5)
MEM0_DQ6: R45.1(N1) U12.L1(MEM0_DQ6)
MEM0_DQ7: R41.1(N1) U12.K1(MEM0_DQ7)
MEM0_DQ8: R49.1(N1) U12.H2(MEM0_DQ8)
MEM0_DQ9: R54.1(N1) U12.G2(MEM0_DQ9)
MEM0_DQ10: R53.1(N1) U12.H3(MEM0_DQ10)
MEM0_DQ11: R65.1(N1) U12.F3(MEM0_DQ11)
MEM0_DQ12: R44.1(N1) U12.F1(MEM0_DQ12)
MEM0_DQ13: R66.1(N1) U12.E2(MEM0_DQ13)
MEM0_DQ14: R60.1(N1) U12.F2(MEM0_DQ14)
MEM0_DQ15: R61.1(N1) U12.E3(MEM0_DQ15)
MEM0_LDM: R42.1(N1) U13.F8(LDM)
MEM0_LDQS: R52.1(N1) U12.J2(MEM0_LDQS)
MEM0_RASZ: R34.1(N1) U13.G9(~{RAS})
MEM0_UDM: R48.1(N1) U13.F2(UDM)
MEM0_UDQS: R43.1(N1) U12.G1(MEM0_UDQS)
MEM0_WEZ: R29.1(N1) U13.G7(~{WE})
MEM_T_A0: R31.2(N2) U12.P1(MEM0_A0)
MEM_T_A1: R30.2(N2) U12.R3(MEM0_A1)
MEM_T_A2: R26.2(N2) U12.R1(MEM0_A2)
MEM_T_A3: R25.2(N2) U12.R2(MEM0_A3)
MEM_T_A4: R79.2(N2) U12.A1(MEM0_A4)
MEM_T_A5: R59.2(N2) U12.B1(MEM0_A5)
MEM_T_A6: R80.2(N2) U12.A2(MEM0_A6)
MEM_T_A7: R64.2(N2) U12.B2(MEM0_A7)
MEM_T_A8: R62.2(N2) U12.D2(MEM0_A8)
MEM_T_A9: R81.2(N2) U12.A3(MEM0_A9)
MEM_T_A10: R32.2(N2) U12.P2(MEM0_A10)
MEM_T_A11: R82.2(N2) U12.B3(MEM0_A11)
MEM_T_A12: R63.2(N2) U12.D3(MEM0_A12)
MEM_T_BA0: R40.2(N2) U12.M3(MEM0_BA0)
MEM_T_BA1: R27.2(N2) U12.P3(MEM0_BA1)
MEM_T_CASZ: R24.2(N2) U12.R4(MEM0_CASZ)
MEM_T_CKE: R57.2(N2) R58.2(N2) U12.C1(MEM0_CKE)
MEM_T_CLK_N: R55.2(N2) U12.E1(MEM0_CLK_N)
MEM_T_CLK_P: R56.2(N2) U12.D1(MEM0_CLK_P)
MEM_T_CSZ: R28.2(N2) U12.J3(MEM0_CSZ)
MEM_T_DQ0: R35.2(N2) U13.A8(DQ0)
MEM_T_DQ1: R50.2(N2) U13.B7(DQ1)
MEM_T_DQ2: R33.2(N2) U13.B8(DQ2)
MEM_T_DQ3: R46.2(N2) U13.C7(DQ3)
MEM_T_DQ4: R51.2(N2) U13.C8(DQ4)
MEM_T_DQ5: R47.2(N2) U13.D7(DQ5)
MEM_T_DQ6: R45.2(N2) U13.D8(DQ6)
MEM_T_DQ7: R41.2(N2) U13.E7(DQ7)
MEM_T_DQ8: R49.2(N2) U13.E3(DQ8)
MEM_T_DQ9: R54.2(N2) U13.D2(DQ9)
MEM_T_DQ10: R53.2(N2) U13.D3(DQ10)
MEM_T_DQ11: R65.2(N2) U13.C2(DQ11)
MEM_T_DQ12: R44.2(N2) U13.C3(DQ12)
MEM_T_DQ13: R66.2(N2) U13.B2(DQ13)
MEM_T_DQ14: R60.2(N2) U13.B3(DQ14)
MEM_T_DQ15: R61.2(N2) U13.A2(DQ15)
MEM_T_LDM: R42.2(N2) U12.J1(MEM0_LDM)
MEM_T_LDQS: R52.2(N2) U13.E8(LDQS)
MEM_T_RASZ: R34.2(N2) U12.P4(MEM0_RASZ)
MEM_T_UDM: R48.2(N2) U12.H1(MEM0_UDM)
MEM_T_UDQS: R43.2(N2) U13.E2(UDQS)
MEM_T_WEZ: R29.2(N2) U12.R5(MEM0_WEZ)
P1P0V: C2.1(P) C13.1(P) C14.1(P) C104.1(P) C105.1(P) C106.1(P) C107.1(P) C108.1(P) C109.1(P) C110.1(P) F101.1(N1) L1.2 R2.2(N2) TP2.1(P1) U12.D5(VDD) U12.D9(VDD) U12.F4(VDD) U12.F12(VDD) U12.J4(VDD) U12.J12(VDD) U12.M6(VDD) U12.M8(VDD) U12.M11(VDD)
P1P0V_FB: R1.1(N1) R2.1(N1) U1.4(FB)
P1P0V_SW: L1.1 U1.5(SW)
P1P8V: C3.1(P) C4.1(P) C5.1(P) C6.1(P) C7.1(P) C10.1(P) C15.1(P) C16.1(P) C17.1(P) C24.1(P) C100.1(P) C101.1(P) C102.1(P) C103.1(P) C112.1(P) C113.1(P) C114.1(P) C115.1(P) C116.1(P) C117.1(P) C126.1(P) C128.1(P) C130.1(P) J1.1(P1) J1.2(P2) J1.21(P21) J1.22(P22) J1.41(P41) J1.42(P42) L2.2 R70.1(N1) R71.2(N2) R84.2(N2) R103.1(N1) R104.1(N1) R108.2(N2) R109.2(N2) R110.1(N1) R116.1(N1) TP23.1(P1) U5.B5(VSPI) U11.4(VIN) U11.6(VIN) U12.C4(VCC_18) U12.D6(VCC_FLSH) U12.D8(VCC_18) U12.E4(VCC_18) U12.G3(VCC_18) U12.K3(VCC_18) U12.K12(VCC_18) U12.L4(VCC_18) U12.M5(VCC_18) U12.M9(VCC_18) U12.M12(VCC_18) U12.N4(VCC_18) U12.N12(VCC_18) U13.A7(VDDQ) U13.A9(VDD) U13.B1(VDDQ) U13.C9(VDDQ) U13.D1(VDDQ) U13.E9(VDDQ) U13.F9(VDD) U13.K9(VDD)
P1P8V_FB: R83.1(N1) R84.1(N1) U2.4(FB)
P1P8V_SW: L2.1 U2.5(SW)
P2P5V: C44.1(P) C132.1(P) C134.1(P) D2.2(P2) R90.1(N1) R95.2(N2) U6.5(VCC) U7.5(OUT) U8.5(PWR)
PARKZ: R116.2(N2) U5.B4(INTZ) U12.B8(PARKZ)
PCLK: P1.28(P28) U12.D13(PCLK)
PDM_CVS_TE: TP15.1(P1) U12.H15(PDM_CVS_TE)
PROJ_ON: U5.E6(PROJ_ON) U6.2(A) U10.4(Y)
PROJ_ON_EXT: P2.15(P15) U10.1(A)
PROJ_ON_S/A: U9.2(~{RESET}) U10.6(C)
PWM_IN: R87.2(N2) U5.D5(PWM_IN)
PWR_EN: U1.3(EN) U2.3(EN) U5.D3(PWR_EN)
PWR_SUPERVISOR: R125.1(N1) U9.3(VDD)
R[0]: P1.14(P14) U12.A14(PDATA_16)
R[1]: P1.11(P11) U12.B13(PDATA_17)
R[2]: P1.15(P15) U12.A13(PDATA_18)
R[3]: P1.45(P45) U12.C12(PDATA_19)
R[4]: P1.46(P46) U12.B12(PDATA_20)
R[5]: P1.43(P43) U12.A12(PDATA_21)
R[6]: P1.44(P44) U12.C11(PDATA_22)
R[7]: P1.41(P41) U12.B11(PDATA_23)
RED_CATHODE: JLEDFLEX.3(P3) JLEDFLEX.4(P4) TP29.1(P1) U5.G5(SW4)
REF_VRST: R93.2(N2) U5.B6(REF_VRST)
RESETZ: TP24.1(P1) U5.B3(RESETZ) U12.J14(RESETZ)
RLIM: R92.1(N1) U5.F5(RLIM_K) U5.F6(RLIM_1) U5.F7(RLIM_2)
RTSZ: R90.2(N2) U5.F4(RSTZ)
S_STAT_LED: D2.1(P1) R129.1(N1)
S_STAT_LEDDRV: R129.2(N2) U8.4(Y)
SBPWR_FB: R94.2(N2) R95.1(N1) U7.1(FB/NC)
SBPWR_IN: C133.1(P) R128.1(N1) U7.4(IN)
SCL: P2.19(P19) R119.1(N1) U4.6(SCL) U12.A10(DBIC_SCL)
SDA: P2.20(P20) R118.1(N1) U4.5(SDA) U12.C10(DBIC_SDA)
SEL_A0: J5.2 R123.1(N1) U4.1(A0)
SEL_A1: J4.2 R122.1(N1) U4.2(A1)
SEL_A2: R121.1(N1) U4.3(A2)
SENS1: TP32.1(P1) U5.E4(SENS1)
SENS2: C37.1(P) R91.2(N2) U5.E5(SENS2)
SPICLK: R78.1(N1) R111.2(N2) U3.6(CLK) U5.C3(SPI_CLK)
SPICSZ0: R76.1(N1) R104.2(N2) U3.1(/CS)
SPICSZ1: R75.1(N1) R110.2(N2) U5.C4(SPI_CSZ)
SPIMISO: R112.2(N2) U3.2(DO) U5.C6(SPI_DOUT) U12.B4(SPIDIN)
SPIMOSI: R77.1(N1) U3.5(DI) U5.C5(SPI_DIN)
STAT_DRV: R126.2(N2) U6.4(Y)
STAT_LED: D3.2(P2) R126.1(N1)
SWN: D1.1(P1) L4.2 U5.A5(SWN)
SWP: L4.1 U5.A7(SWP)
SYSPWR: C1.2(N) C8.2(N) C9.2(N) C11.2(N) C12.2(N) C18.2(N) C19.2(N) C20.2(N) C21.2(N) C23.2(N) C28.1(P) C29.1(P) C30.1(P) C31.1(P) C32.1(P) C41.1(P) C43.1(P) C129.1(P) J2.1(PIN) J3.1 R96.2(N2) R97.2(N2) R117.1(N1) R124.1(N1) R125.2(N2) R128.2(N2) U1.1(VIN) U2.1(VIN) U5.A1(VINL_1) U5.A2(VINL_2) U5.A4(VINR)
SYSPWR_SHUNT: J2.3(SHUNT) R124.2(N2)
THERMISTOR_P: R89.1(N1) R91.1(N1) RT1.1 TP33.1(P1)
TSTPT_0: TP25.1(P1) U12.B6(TXD_TSTPT_0)
TSTPT_1: TP21.1(P1) U12.A8(GPO0_TSTPT_1)
TSTPT_2: TP19.1(P1) U12.C7(GPO1_TSTPT_2)
TSTPT_3: TP27.1(P1) U12.B5(GPO2_TSTPT_3)
TSTPT_4: TP22.1(P1) U12.A7(GPO3_TSTPT_4)
TSTPT_5: TP20.1(P1) U12.C8(GPO4_TSTPT_5)
TSTPT_6: TP6.1(P1) U12.N9(IRW_EN_TSTPT_6)
TSTPT_7: TP3.1(P1) U12.R9(IRW_SYNC_TSTPT_7)
VBIAS: C40.1(P) R68.1(N1) U5.B7(VBIAS)
VOFS: C39.1(P) R107.1(N1) U5.C7(VOFS)
VRST: C42.1(P) D1.2(P2) R69.1(N1) R93.1(N1)
VSYNC: P1.27(P27) U12.H14(VSYNC_WE)
X_OUT1: C122.1(P) R102.2(N2) XD100.1(P)
N16791220: R96.1(N1) U10.5(VCC)
N16866908: R120.1(N1) U4.7(WP)

Not connected (* = marked no-connect by the designer): J1 39(P39); P1 3(P3) 4(P4) 5(P5) 6(P6) 7(P7) 8(P8) 9(P9) 10(P10) 20(P20) 21(P21) 22(P22) 23(P23) 24(P24) 25(P25); P2 4(P4) 5(P5) 6(P6) 7(P7) 8(P8) 9(P9) 10(P10) 11(P11) 12(P12) 13(P13) 14(P14) 16(P16) 17(P17) 18(P18) 21(P21) 22(P22) 23(P23) 24(P24) 25(P25) 26(P26) 27(P27) 28(P28) 29(P29) 30(P30) 31(P31) 32(P32) 33(P33) 34(P34) 35(P35) 36(P36) 37(P37) 38(P38) 39(P39) 40(P40) 41(P41) 42(P42); U7 3(NC)*; U12 C2(NCC2)* C3(NCC3)* K14(DMD_PWR_EN)* N2(NCN2)* N3(NCN3)*; U13 F3(NC)*

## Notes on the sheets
sheet 1
- SDRAM mDDR MEMORY (JEDEC FOOTPRINT)
- *All resistor values in this page are 30 Ohms unless otherwise noted
- R's close to
  DPP pins
- This R close to
  MEM pins
- PRELIMINARY
sheet 2
- Revisions
- Rev. A : Initial Release
- REVISION NOTES
- PRELIMINARY
sheet 3
- DESIGN NOTES:
  * See DPP2601/7 Datasheet for PCB Layout Guidelines.
- DLPC2607 Clock, Reset, SPI
- 16Mbit Flash Memory
- 16.66667MHz
- DLPC2607 I/Os, GPIOs, Testpoints
- I2C I/F
- PRELIMINARY
sheet 4
- DLPC2607 DATA INTERFACE
- DLPC2607 DMD INTERFACE
- CONNECTOR FOR DMD FLEX CABLE
- DMD POWER SUPPLY
- * Please place capacitors close to the DMD Flex Cable Connector
sheet 5
- POWER MANAGEMENT - PAD1000
- POWER REGULATORS
- FB=0.6V
- FB=0.6V
- VOFS=8.5V
- VBIAS=16V
- VRST=-10V
- VFB=1.205V
  VOUT=2.5V
- EXTERNAL POWER INPUT
- 5V
  5A MAX
- DLPC2607 power pins and
  their decoupling capacitors.
- CONNECTOR FOR
  THE RGB LED FLEX
- Gentle power down capacitors
- pin 2 - sleeve
- pin 1 - pin
- pin 3 - shunt
- jack insert direction
- PRELIMINARY
sheet 6
- BOARD INTERFACE CONNECTORS
- EEPROM IC
- PRELIMINARY
sheet 7
- PRELIMINARY
     03/07/2017
- ESD – DWG# 2515209/ ECO# TBD
  PCB – DWG# 2515210/ ECO# TBD
  CCA – DWG# 2515211/ ECO# TBD
